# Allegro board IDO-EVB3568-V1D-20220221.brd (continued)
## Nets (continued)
S7TX_M1/RS485-B7: D87.1 D104.A(I/O2) F9.1 L44.2 R297.1
S7TX_M1_: F9.2 J36.2 TP11.1
SARADC_VIN0_KEY/RECOVERY: D33.1(I/O2) M5.15(SARADC_VIN0_KEY/RECOVERY) R62.1
SARADC_VIN2_HP_HOOK: C81.2 D35.1(I/O2) J13.3 M5.16(SARADC_VIN2_HP_HOOK) R70.2 R71.1
SARADC_VIN4: D36.1(I/O2) J13.4 M5.17(SARADC_VIN4) R60.2
SARADC_VIN5: D37.1(I/O2) J13.5 M5.18(SARADC_VIN5) R61.2
SATA1_RXN: C50.1 J6.5(RXN)
SATA1_RXP: C51.1 J6.6(RXP)
SATA1_TXN: C47.1 J6.3(TXN)
SATA1_TXP: C46.1 J6.2(TXP)
SCL_CAM: J28.7 R144.2
SD_CLK: C34.2 D9.1(I/O2) J3.5(CLK) R21.2
SD_CMD: D7.1(I/O2) J3.3(CMD) R20.2
SD_D0: D3.1(I/O2) J3.7(DATA0) R22.2
SD_D1: D4.1(I/O2) J3.8(DATA1) R23.2
SD_D2: D5.1(I/O2) J3.1(DATA2) R18.2
SD_D3: D6.1(I/O2) J3.2(CD/DATA3) R19.2
SDA_CAM: J28.8 R145.2
SDMMC0_CLK: M5.63(SDMMC0_CLK/TEST_CLKOUT/UART5_TX) R21.1
SDMMC0_CMD: M5.64(SDMMC0_CMD/PWM10_M1/UART5_RX_M0) R20.1
SDMMC0_D0: M5.68(SDMMC0_D0/UART2_TX_M1/UART6_TX_) R22.1
SDMMC0_D1: M5.67(SDMMC0_D1/UART2_RX_M1/UART6_RX_) R23.1
SDMMC0_D2: M5.66(SDMMC0_D2/ARMJTAG_TCK/UART5_CTS) R18.1
SDMMC0_D3: M5.65(SDMMC0_D3/ARMJTAG_TMS/UART5_RTS) R19.1
SDMMC0_DET_L: M5.62(SDMMC0_DET/SATA_CP_DET/PCIE30X1) R24.1
SDMMC2_CLK_M0: M5.92(CIF_D5/EBC_SDDO5/SDMMC2_CLK_M0/) R159.1
SDMMC2_CMD_M0: M5.93(CIF_D4/EBC_SDDO4/SDMMC2_CMD_M0/) R157.2 R158.1
SDMMC2_D0_M0: M5.97(CIF_D0/EBC_SDDO0/SDMMC2_D0_M0/I) R152.2 R153.1
SDMMC2_D1_M0: M5.96(CIF_D1/EBC_SDDO1/SDMMC2_D1_M0/I) R154.1
SDMMC2_D2_M0: M5.95(CIF_D2/EBC_SDDO2/SDMMC2_D2_M0/I) R155.1
SDMMC2_D3_M0: M5.94(CIF_D3/EBC_SDDO3/SDMMC2_D3_M0/I) R156.1
SIM_CLK: C271.2 D95.1(I/O2) R327.2 SIM1.C3(CLK) U36.32(UIM_CLK)
SIM_DATA: C262.2 D96.1(I/O2) R326.2 R339.1 SIM1.C7(DATA) U36.34(UIM_DATA)
SIM_DET: R325.1
SIM_RST: C272.2 D94.1(I/O2) R329.2 R330.1 SIM1.C2(RESET) U36.30(UIM_RESET)
SPI3_CLK_M1: D98.1(I/O2) J14.3 M5.27(PWM14_M1/SPI3_CLK_M1/CAN1_RX_M1)
SPI3_CS0_M1: D101.1(I/O2) J14.6 M5.31(PWM13_M1/SPI3_CS0_M1/SATA0_ACT_)
SPI3_MISO_M1: D100.1(I/O2) J14.5 M5.30(PWM12_M1/SPI3_MISO_M1/SATA1_ACT)
SPI3_MOSI_M1: D99.1(I/O2) J14.4 M5.28(PWM15_IR_M1/SPI3_MOSI_M1/CAN1_T)
SPK_5V: C92.2 C93.2 L21.2 U13.4(PVDD1) U13.13(PVDD2)
SPK_CTL_H_: Q1.3 U13.12(S\D\)
SPK_MUTE_H_: Q2.3 U13.5(M\U\T\E\)
SYS_LED_GPIO0_C7: M5.26(HDMITX_CEC_M1/PWM0_M1/UART0_CTS) R8.1
TP_INT: D64.1(I/O2) J24.4 R112.2
TP_INT_L_GPIO3_B4: M5.115(LCDC_D19/VOP_BT1120_D10/GMAC1_R) R112.1
TP_RST: D65.1(I/O2) J24.5 R111.2
TP_RST_L_GPIO3_B3: M5.116(LCDC_D18/VOP_BT1120_D9/GMAC1_RX) R111.1
TP_SCL: D63.1(I/O2) J24.3 R113.2
TP_SDA: D62.1(I/O2) J24.2 R114.2
UART0_RX: M5.19(PWM1_M0/GPUAVS/UART0_RX/GPIO0_C) R372.1 R383.1
UART0_RX_: R372.2 U27.9(R2OUT)
UART0_TX: M5.20(PWM2_M0/NPUAVS/UART0_TX/MCU_JTA) R278.1 U27.10(T2IN)
UART2_RX_M0: M5.60(UART2_RX_M0/GPIO0_D0_U) R26.1
UART2_TX_M0: M5.59(UART2_TX_M0/GPIO0_D1_U) R27.1
UART3_RX_M1: M5.111(LCDC_D23/PWM13_M0/GMAC1_MCLKINO) R370.1 R384.1
UART3_RX_M1_: R370.2 U26.12(R1OUT)
UART3_TX_M1: M5.112(LCDC_D22/PWM12_M0/GMAC1_TXEN_M0) R282.1 U26.11(T1IN)
UART4_RX_M1: M5.118(LCDC_D16/VOP_BT1120_D7/GMAC1_RX) R371.1 R385.1
UART4_RX_M1_: R371.2 U26.9(R2OUT)
UART4_TX_M1: M5.117(LCDC_D17/VOP_BT1120_D8/GMAC1_RX) R284.1 U26.10(T2IN)
UART5_RX_M1: D82.A M5.108(LCDC_DEN/VOP_BT1120_D15/SPI1_CL) R287.2 R373.1
UART5_RX_M1_: R373.2 U27.12(R1OUT)
UART5_TX_M1: D84.C M5.109(LCDC_VSYNC/VOP_BT1120_D14/SPI1_) R286.1 R288.1 U27.11(T1IN)
UART7_RX_M1: D86.A M5.106(PWM15_IR_M0/SPDIF_TX_M1/GMAC1_M) R294.2
UART7_TX_M1: D88.C M5.107(PWM14_M0/VOP_PWM_M1/GMAC1_MDC_M) R291.1 R295.1
UART8_CTSN_M0: M5.46(SDMMC1_DET/I2C4_SCL_M1/UART8_CT) R173.1 U23.41(UART_RTS_N)
UART8_RTSN_M0: M5.45(SDMMC1_PWREN/I2C4_SDA_M1/UART8_) U23.44(UART_CTS_N)
UART8_RX_M0: M5.58(CLK32K_OUT1/UART8_RX_M0/SPI1_CS) U23.42(UART_TXD)
UART8_TX_M0: M5.57(I2S2_SDI_M0/GMAC0_RXER/UART8_TX) U23.43(UART_RXD)
USB2_HOST2_DM: M5.99(USB2_HOST2_DM) R51.2
USB2_HOST2_DP: M5.100(USB2_HOST2_DP) R50.2
USB2_HOST3_DM: L7.2 M5.101(USB2_HOST3_DM)
USB2_HOST3_DM_: D18.2 D18.9 J8.2(1D-) L7.3
USB2_HOST3_DP: L7.1 M5.102(USB2_HOST3_DP)
USB2_HOST3_DP_: D18.1 D18.10 J8.3(1D+) L7.4
USB3_HOST1_DM: L6.1 M5.182(USB3_HOST1_DM)
USB3_HOST1_DM_: D15.5 D15.6 J5.11(2D-) L6.4
USB3_HOST1_DP: L6.2 M5.183(USB3_HOST1_DP)
USB3_HOST1_DP_: D15.4 D15.7 J5.12(2D+) L6.3
USB3_HOST1_SSRXN: C50.2 M5.185(USB3_HOST1_SSRXN/SATA1_RXN/QSGM) R32.1
USB3_HOST1_SSRXN_: D17.4 D17.7 J5.14(RX2-) R32.2
USB3_HOST1_SSRXP: C51.2 M5.184(USB3_HOST1_SSRXP/SATA1_RXP/QSGM) R33.1
USB3_HOST1_SSRXP_: D17.5 D17.6 J5.15(RX+) R33.2
USB3_HOST1_SSTXN: C40.1 C47.2 M5.181(USB3_HOST1_SSTXN/SATA1_TXN/QSGM)
USB3_HOST1_SSTXN_: C40.2 D16.4 D16.7 J5.17(TX2-)
USB3_HOST1_SSTXP: C42.1 C46.2 M5.180(USB3_HOST1_SSTXP/SATA1_TXP/QSGM)
USB3_HOST1_SSTXP_: C42.2 D16.5 D16.6 J5.18(TX2+)
USB3_OTG0_DM: L5.1 M5.188(USB3_OTG0_DM)
USB3_OTG0_DM_: D15.2 D15.9 J5.2(1D-) L5.4
USB3_OTG0_DP: L5.2 M5.189(USB3_OTG0_DP)
USB3_OTG0_DP_: D15.1 D15.10 J5.3(1D+) L5.3
USB3_OTG0_ID: M5.193(USB3_OTG0_ID)
USB3_OTG0_SSRXN: M5.191(USB3_OTG0_SSRXN/SATA0_RXN) R30.1
USB3_OTG0_SSRXN_: D17.1 D17.10 J5.5(RX1-) R30.2
USB3_OTG0_SSRXP: M5.190(USB3_OTG0_SSRXP/SATA0_RXP) R31.1
USB3_OTG0_SSRXP_: D17.2 D17.9 J5.6(RX1+) R31.2
USB3_OTG0_SSTXN: C36.1 M5.187(USB3_OTG0_SSTXN/SATA0_TXN)
USB3_OTG0_SSTXN_: C36.2 D16.1 D16.10 J5.8(TX1-)
USB3_OTG0_SSTXP: C37.1 M5.186(USB3_OTG0_SSTXP/SATA0_TXP)
USB3_OTG0_SSTXP_: C37.2 D16.2 D16.9 J5.9(TX1+)
USB3_OTG0_VBUSDET: M5.192(USB3_OTG0_VBUSDET) R28.1 R29.1
USB_OTG_PWREN_H: M5.61(SDMMC0_PWREN/SATA_MP_SWITCH/PCI) R34.1 U4.4(EN)
VOLN: C87.1 D46.1(I/O2) J17.4 L17.2 TP27.1
VOLP: C88.1 D45.1(I/O2) J17.3 L18.2 TP26.1
VORN: C90.1 D44.1(I/O2) J17.2 L19.2 TP25.1
VORP: C91.1 D43.1(I/O2) J17.1 L20.2 TP24.1
WIFI1T1R_CLK: C153.2 R159.2 U23.17(SDIO_DATA_CLK)
WIFI1T1R_CMD: R158.2 U23.16(SDIO_DATA_CMD)
WIFI1T1R_D0: R153.2 U23.18(SDIO_DATA_0)
WIFI1T1R_D1: R154.2 U23.19(SDIO_DATA_1)
WIFI1T1R_D2: R155.2 U23.14(SDIO_DATA_2)
WIFI1T1R_D3: R156.2 U23.15(SDIO_DATA_3)
WIFI1T1R_XTAL_IN: C155.1 U23.10(XTAL_IN) XT3.3
WIFI1T1R_XTAL_OUT: R163.2 U23.11(XTAL_OUT)
WIFI_REG_ON_H_GPIO3_D4: M5.91(CIF_D6/EBC_SDDO6/SDMMC2_DET_M0/) R168.1 R182.1
WIFI_WAKE_HOST_H_GPIO3_D5: M5.90(CIF_D7/EBC_SDDO7/SDMMC2_PWREN_M) U23.13(WL_HOST_WAKE)
WIFIBT_32KIN_1T1R: C168.2 R176.2 R177.2 U23.24(LPO)
N17052705: R179.1 U23.29(VDD_TCXO)
N17052995: R181.2 R182.2 U23.34(BT_RST_N)
N17053074: C154.2 C156.2 U23.2(WL_BT_ANT)
N17053234: C154.1 C157.2 J29.2(SIG)
N17053342: C167.2 C491.2 L31.2 U23.23(VIN_LDO)
N17053374: C158.2 R163.1 XT3.1
N17053434: L31.1 U23.21(VIN_LDO_OUT)
N17846666: R215.1 U24.31(INTB/PMEB)
N67123537: R35.1 U4.3(OCB)
N67146313: R46.1 U8.43(OVCJ5) U8.45(OVCJ1)
N67159131: R41.1 U6.3(OCB)
N67228394: C2.1 L1.1 U1.2(LX)
N67228398: C2.2 U1.4(BS)
N67228404: C8.1 R4.2 R6.1 U1.6(FB)
N67269040: D60.A L28.2 U16.1(LX)
N67928236: C218.2 U26.1(C1+)
N67928238: C218.1 U26.3(C1-)
N67928242: C219.2 U26.4(C2+)
N67928244: C219.1 U26.5(C2-)
N67928270: C220.2 U26.2(V+)
N67928274: C221.2 U26.6(V-)
N68112138: R37.1 U5.3(OCB)
N68117516: D12.1(I/O2) J4.2 R27.2
N68117520: D10.C D11.1(I/O2) J4.1
N68117689: D10.A R25.2 R26.2
N68120764: D49.C R82.1 R84.1
N68141872: R115.1 U16.3(FB)
N68149060: R62.2 SW1.1
N68226715: L34.1 U26.14(T1OUT)
N68226717: L35.1 U26.13(R1IN)
N68226719: L36.1 U26.7(T2OUT)
N68226721: L37.1 U26.8(R2IN)
N68234263: D38.1(I/O2) J15.3(R) R76.2
N68234265: D40.1(I/O2) J15.2(L) R73.2
N68234885: C80.2 R68.2 R69.1
N68235937: D39.1(I/O2) J15.5(L-COM) R74.2
N68290667: L18.1 U13.1(VOLP)
N68290669: L17.1 U13.3(VOLN)
N68290717: L19.1 U13.14(VORN)
N68290719: L20.1 U13.16(VORP)
N68290721: C86.1 R79.1
N68290723: R79.2 U13.7(INL)
N68290736: C89.1 R80.1
N68290738: R80.2 U13.10(INR)
N68290823: C85.2 U13.8(BYPASS)
N68391184: R14.2 U2.1(EN)
N68391237: L2.1 U2.3(SW)
N68391239: C19.1 R12.2 R15.1 U2.5(FB)
N68444772: C488.2 D1.C F1.2 L50.2 R368.1
N68540703: R262.1 U25.31(INTB/PMEB)
N68550545: C126.2 C129.2 U17.11(VCORE)
N68551303: R121.2 U17.8(I2C_TYPE)
N68551306: R122.2 U17.12(EN)
N68551396: R120.2 U17.7(I2C_ADDR)
N68552374: C141.1 Q9.1(GATE) R129.2 R131.2
N68552446: Q10.3 R131.1
N68558276: R104.1 U15.3(FB)
N68558638: D56.A L27.2 U15.1(LX)
N68563618: C239.1 U34.1(OSCI) XT6.1
N68563661: C240.1 U34.2(OSCO) XT6.2
N68582360: C111.1 Q6.1(GATE) R90.2 R91.2
N68582430: Q7.3 R91.1
N68600227: J41.10(USIM_IO) R326.1
N68600229: J41.12(USIM_CLK) R327.1
N68600231: J41.14(USIM_RESET) R329.1
N68600309: J41.8(VREG_USIM) L48.1
N68610828: C165.1 Q12.1(GATE) R175.2 R178.2
N68611164: Q13.3 R178.1
N68644173: R168.2 U23.12(WL_REG_ON)
N68693421: R43.1 U7.3(OCB)
N68696061: R49.1 U9.3(OCB)
N68696295: R53.1 U10.3(OCB)
N68706836: R57.1 U11.3(OCB)
N68707388: R59.1 U12.3(OCB)
N68721096: R325.2 U36.66(SIM1_DETECT_(1V8))
N68721887: R342.2 U37.1(EN)
N68721931: L49.1 U37.3(SW)
N68721933: C265.1 R340.2 R341.1 U37.5(FB)
N68723170: C252.2 R337.2 R338.1 U36.6(FUL_CARD_P/OWER_OFF#_(3V3/1V8))
N68753609: R321.2 U35.24(SDA/SDI)
N68753612: R322.1 U35.22(NCS)
N68753720: R320.2 U35.23(SCL/SCLK)
N68753740: TP1.1 U35.12(INT)
N68754791: C245.2 U35.10(REGOUT)
N68764417: C16.1 L3.1 U39.2(LX)
N68764421: C16.2 U39.4(BS)
N68764430: C24.1 R13.2 R17.1 U39.6(FB)
N68782340: R149.2 U19.3(EN)
N68782427: R150.2 U20.3(EN)
N68782451: R151.2 U21.3(EN)
N68784083: C83.2 R75.2 R78.1
N68821934: LED1.1 R8.2
N68821936: LED1.3 R9.2
N68825811: LED2.A(ANODE) R334.2
N68865571: C227.2 D84.A R288.2 U28.2
N68866830: C230.2 D88.A R295.2 U30.2
N68869057: C223.2 U27.1(C1+)
N68869059: C223.1 U27.3(C1-)
N68869063: C224.2 U27.4(C2+)
N68869065: C224.1 U27.5(C2-)
N68869069: C225.2 U27.2(V+)
N68869073: C226.2 U27.6(V-)
N68869089: L38.1 U27.14(T1OUT)
N68869091: L39.1 U27.13(R1IN)
N68869093: L40.1 U27.7(T2OUT)
N68869095: L41.1 U27.8(R2IN)
N68871128: C235.2 R303.2 R304.2
N68871171: C234.2 R300.2 U32.5(VIO/NC)
N68877118: C238.2 R310.2 R311.2
N68877190: C237.2 R367.2 U33.5(VIO/NC)
N68886075: C202.2 J31.1(CT1/2/3/4)
N68888039: C179.2 J30.1(CT1/2/3/4)
N69126369: J41.22(PERST_N) R376.1
N69153757: C12.2 R3.2 R5.1 U39.5(EN)
N69164567: R16.2 U1.5(EN)
N69167857: R381.1 U40.3(OCB)
N69206132: R386.1 R389.2 U19.4(NC)
N69206262: C492.2 R387.2 R388.1 U20.4(NC)
N69206971: R390.1 R391.2 U21.4(NC)

Pads without a net: D71 5; D72 5; D73 5; D74 5; J2 5 6; J15 6; J18 14; J19 3 5 6; J22 3 4 5 6 7 8 12 13 14 15 17 18 35 40; J23 3 4 5 6 7 8 12 13 14 15 17 18 35 40; J26 4; J41 1 3 5 6 7 11 13 16 17 19 20 23 25 28 30 31 32 33 44 45 46 47 48 49 51; M1 1; M2 1; M3 1; M4 1; M5 205 206 207; SIM1 C6 CD1 CD2; U8 1 2 3 4 5 7 44 46 47 48; U17 1 2 3 4 6; U23 4 5 8 25 26 27 28 30 32 35 37 38 39 40 45 46 47; U28 1; U30 1; U34 3; U35 1 2 3 4 5 6 7 14 15 16 17 19 21; U36 1 7 8 9 10 20 21 22 23 24 25 26 28 29 31 35 37 38 40 42 44 46 48 50 52 54 56 58 59 60 61 62 63 64 65 68 69 75

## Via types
v1: diameter 0.55, hole 0.3, TOP to BOTTOM, 807 vias
v2: diameter 0.406, hole 0.203, TOP to BOTTOM, 1303 vias

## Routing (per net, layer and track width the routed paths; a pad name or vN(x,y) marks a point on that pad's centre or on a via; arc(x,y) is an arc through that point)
GND: length 3029.4
  TOP w0.127: v2(91.08,25.53) 91.44,25.88 91.44,27.94 92.46,28.96 92.46,37.59 92.96,38.1 92.96,41.02 92.46,41.53 92.46,50.52 93.09,51.16 93.09,51.61 93.91,52.43 v2(94.59,52.43) ; v2(76.83,24.49) v2(76.83,25.65) 76.83,26.16 77.22,26.54 80.01,26.54 87.88,34.42 87.88,53.19 v2(88.04,53.34) 88.04,54 88.27,54.23 88.77,54.23 88.9,54.1 88.9,53.37 v2(88.87,53.34) 88.87,53.19 88.39,52.7 88.39,34.16 80.26,26.04 79.01,26.04 v2(78.87,25.9) 78.49,25.51 78.49,25.15 78.87,24.77 80.14,24.77 81.41,26.04 ; M5.98 96.8,64.24 99.59,61.44 v2(99.59,59.44) ; v2(89.66,26.04) 89.66,27.69 91.44,29.46 91.44,38.23 91.69,38.48 v1(91.69,38.95) ; v2(90.73,24.54) 90.73,24.84 90.42,25.15 90.42,27.69 91.95,29.21 91.95,37.85 92.46,38.35 92.46,40.77 91.95,41.27 91.95,50.73 92.58,51.37 92.58,51.82 94.16,53.39 v2(94.34,53.39) ; v2(92.96,62.99) 94.36,61.59 94.36,53.42 v2(94.34,53.39) ; v2(95.76,22.05) 95.76,22.99 96.52,23.75 97.54,23.75 98.3,24.51 98.3,31.37 99.19,32.26 99.19,43.43 102.49,46.74 115.21,46.74 116.61,48.13 126.75,48.13 126.98,48.36 127,48.36 127.77,49.14 127.77,49.16 ; v2(94.34,53.39) 94.74,52.98 94.74,52.58 v2(94.59,52.43) ; 81.41,26.04 89.15,33.78 89.15,52.2 89.79,52.83 89.79,53.21 91.44,54.86 91.44,55.88 91.19,56.13 91.19,58.17 91.72,58.7 v2(91.92,58.7) 92.29,58.33 92.29,57.87 91.97,57.55 v2(91.89,57.55) 91.69,57.35 91.69,56.52 92.08,56.13 92.08,54.74 90.3,52.96 90.3,52.58 89.66,51.94 89.66,33.53 88.77,32.64 88.77,32.13 v2(83.82,27.18) 82.55,25.91 v2(81.92,25.91) 81.53,25.91 81.41,26.04 ; v2(91.97,17.53) 91.99,17.51 92.72,17.51 v2(92.99,17.78) ; v2(73.03,32.51) 73.53,32.51 73.83,32.22 73.83,31.87 72.57,30.61 59.44,30.61 55.02,26.19 v2(55.02,25.91) ; v2(92.77,61.81) 93.85,60.72 93.85,53.85 92.08,52.07 92.08,51.69 91.44,51.05 91.44,40.34 91.69,40.09 v1(91.69,39.62) ; v2(101.5,52.4) 100.97,51.87 100.97,50.6 100.18,49.81 v2(100.18,49.55) ; v2(94.59,52.43) 94.74,52.27 94.74,51.82 94.41,51.49 94.36,51.49 ; 94.36,51.49 94.6,51.24 v2(94.6,50.5) 93.73,49.62 v2(93.73,48.13) v2(93.73,47.12) 93.73,46.72 93.47,46.47 93.47,42.04 94.11,41.4 94.11,38.69 v2(94.27,38.52) ; 94.36,51.49 v2(93.95,51.49) 93.6,51.13 93.6,50.93 92.96,50.29 92.96,41.78 93.47,41.27 93.47,38.18 v2(93.96,37.69) ; v2(97.71,21.69) 97.89,21.69 99.82,23.62 99.82,30.61 100.71,31.5 100.71,42.67 103.25,45.21 115.95,45.21 117.35,46.61 128.42,46.61 129.54,45.49 129.54,41.02 131.32,39.24 ; v1(108.33,58.93) 108.7,59.3 U23.20 108.7,60.97 108.43,61.24 108.43,64.74 108.2,64.97 103.2,64.97 103,64.77 103,60.96 103.53,60.43 103.53,60.15
  TOP w0.152: 14.38,21.86 17.4,24.88 C113.1
  TOP w0.203: v2(122.17,60.17) 122.17,59.62 122.15,59.59 122.15,59.43 122.12,59.41 122.12,59.03 121.21,58.12 118.64,58.12 v2(118.29,57.76) ; 123.75,44.02 124.03,43.74 126.72,43.74 126.95,43.5 126.95,39.7 126.75,39.5 124.61,39.5 v2(124.19,39.92) C239.2 123.22,40.89 120.65,40.89 120.51,41.04 120.51,43.16 120.65,43.31 121.74,43.31 U34.4 ; XT3.2 122.43,61.47 v2(122.68,61.72) 122.68,63.88 122.45,64.11 121.01,64.11 v2(120.65,63.75) 120.06,63.17 XT3.4 118.85,62.99 118.57,62.99 118.26,62.69 118.26,62.65 v2(118.11,62.65) 118.16,62.6 118.24,62.6 118.26,62.58 118.26,59.36 v2(118.32,59.31) ; v2(12.17,27.1) 12.17,31.57 v2(12.34,31.75) ; v1(27.41,49.4) 26.81,49.4 U39.3
  TOP w0.254: 47.88,20.07 49.53,20.07 v2(52.07,20.07) v2(56.52,20.07) 59.18,20.07 59.94,19.3 v2(60.2,19.3) v2(61.72,19.3) 63.75,19.3 v2(64.52,18.54) 65.58,17.48 71.25,17.48 v2(71.73,16.99) ; Q7.2 89.41,13.71 89.66,13.96 ; v2(12.34,31.75) 15.82,31.75 18.11,34.04 18.11,35.61 18.44,35.94 U33.2 ; v2(51.94,22.5) v2(53.34,22.5) 53.37,22.5 v2(54.99,22.5) v2(56.64,22.5) v2(57.91,22.5) v2(59.56,22.5) 60.05,22.5 60.83,21.72 65.91,21.72 67.64,19.99 v2(75.69,19.99) v2(87.88,19.99) v2(88.52,19.99) 88.7,19.99 89.08,19.61 91.39,19.61 91.74,19.25 97.59,19.25 v2(98.3,18.54) 101.73,15.11 103.38,15.11 103.91,14.58 D38.2 ; C131.1 29.66,22.28 v2(29.79,22.4) ; 95.58,3.78 95.53,3.78 94.49,4.83 94.49,5.71 92.58,7.62 92.58,12.19 91.34,13.44 D41.2 ; 95.58,3.78 99.77,3.78 ; 95.58,3.78 95.58,1.98 95.12,1.52 92.71,1.52 92.46,1.78 92.46,3.68 93.6,4.83 93.6,5.33 91.82,7.11 91.82,11.81 90.37,13.26 90.26,13.26 90.24,13.28 89.99,13.28 89.98,13.28 89.97,13.28 89.66,13.59 89.66,13.96 ; 89.66,13.96 v2(89.66,14.22) ; U17.37 19.81,19.68 ; v2(92.99,17.78) 93.24,18.03 95.89,18.03 97.03,16.89 v2(97.03,16.74) 97.18,16.74 98.55,15.37 98.55,14.43 R77.2 ; v2(91.97,17.53) 91.92,17.48 87.35,17.48 v2(86.97,17.09) 86.64,16.76 83.19,16.76 82.47,17.48 76.02,17.48 v2(75.82,17.27) 75.62,17.48 72.72,17.48 v2(72.26,17.02) ; U39.3 26.79,49.9 27.05,50.16 ; M5.14 50.39,23.85 58.8,32.26 v2(67.18,32.26) 67.31,32.38 71.5,32.38 71.63,32.51 v2(73.03,32.51)
  TOP w0.305: v2(112.65,24) 112.69,23.96 U36.57 ; J18.8 v1(28.65,94.49) ; U36.5 v2(125.69,23.88) ; U36.11 v2(124.19,23.86) ; J18.11 v1(30.15,94.49) ; v1(33.15,94.49) J18.17 33.15,91.06 v1(33.4,90.81) ; v1(60.66,84.79) 60.16,85.28 C6.1 ; v1(54.83,85.18) C10.1 v1(54.83,83.25) C11.1 54.83,81.95 v1(55.37,81.41) ; J18.2 v1(25.65,94.49) ; v2(126.19,23.88) U36.3 ; U18.3 29.46,12.25 29.21,12.5 ; U36.73 v2(108.69,23.9) ; U36.71 v2(109.19,23.9) ; U36.45 v2(115.69,23.87) ; U17.9 23.81,23.81 U17.49 23.31,21.81 U17.5 ; U36.51 v2(114.19,21.61) ; J18.5 v1(27.15,94.49)
  TOP w0.381: v2(121.79,17.27) 122.2,17.27 D9.2 ; v2(11.99,52.86) 11.91,52.86 11.46,52.4 C228.1 ; v2(91.62,80.31) U10.2 v2(93.4,80.31) ; 101.9,4.11 J15.1 100.81,2.75 99.77,3.78 ; D43.2 v2(114.17,11.94) ; D14.2 52.88,84.62 v2(52.81,84.69) ; v2(104.44,68.05) 104.17,68.05 R195.1 104.14,68 103.41,67.26 C190.1 ; v2(122.17,60.17) C155.2 121.46,60.66 121.82,61.02 XT3.2 ; v2(118.49,27.69) 119.18,27.69 119.45,27.41 J41.27 ; v2(108.03,23.89) 107.99,23.89 107.99,23.89 107.45,23.89 U36.MTG77 v2(107.1,21.88) ; v2(114.83,68.2) 115.21,68.58 C196.1 ; v2(123.88,18.85) 124.32,18.85 124.52,18.64 C35.1 124.4,18.41 124.24,18.26 v2(123.88,18.26) ; v2(112.62,71.93) 112.62,71.88 112.37,71.63 111.63,71.63 v2(111.46,71.45) ; C222.1 21.77,64.09 v2(21.94,64.26) ; U36.39 117.19,21.87 v2(117.6,21.46) ; J41.15 111.76,26.08 112.14,26.46 v2(112.14,26.8) ; D69.3 21.64,13.74 v2(21.49,13.89) ; v2(130.68,25.65) 131.95,25.65 132.3,26 J41.55 ; J17.5 v2(115.99,4.19) ; J17.5 117.34,2.02 ; J17.5 114.82,2.02 ; J34.1 7.52,54 v2(8.33,53.19) ; D70.3 v2(15.54,13.92) ; J41.50 v2(128.65,35.62) 128.59,35.69 v2(128.14,35.69) v2(127.51,35.69) 127.25,35.69 ; 13.13,24.89 13.26,24.89 v1(13.56,25.2) ; 13.13,24.89 v1(13.56,24.46) ; 13.13,24.89 U15.2 ; R301.1 11.58,43.35 v1(11.58,43.35) 11.58,44.02 C234.1 ; v2(7.37,17.99) 6.31,17.99 5.92,17.61 J39.3 ; v2(118.93,14.93) J3.10 v2(118,13.83) ; D48.3 D48.8 v1(29.46,90.58) ; U23.31 v2(104.65,51.55) 104.58,51.55 R161.2 ; C82.1 v2(97.03,16.74) ; v2(116.43,73.3) 117.2,72.54 R259.1 ; R307.1 11.3,35.05 11.69,35.43 v2(12.29,35.43) ; J41.26 v2(119.05,35.53) ; U33.2 20.39,35.94 20.45,35.99 C236.1 v2(21.03,35.08) ; J33.6 v2(2.17,74.17) ; v2(128.78,24.7) 128.21,24.7 127.8,24.3 U36.MTG76 ; J41.37 v2(123.45,24.77) ; v1(73.66,82.25) 73.46,82.45 D18.3 D18.8 ; U36.MTG76 127.8,22.95 128.14,22.61 v2(128.78,22.61) ; U36.MTG76 v2(128.78,23.55) ; v2(92.43,76.61) 92.43,77.07 R53.2 ; v2(109.35,73.91) 108.99,73.56 C189.1 ; v2(133.53,12.7) J3.11 v2(134.73,13.83) ; v2(114.05,39.75) C263.1 ; J41.34 122.25,35.46 v2(122.05,35.66) ; v2(1.52,78.65) 1.52,78.61 2.17,77.96 J32.5 ; v2(104.8,49.75) U23.33 ; v2(95.19,82.3) C61.1 v2(95.81,83.06) ; v2(13.03,55.55) U29.5 v2(15.06,55.55) ; J39.6 v2(4.31,10.8) ; C226.1 v2(11.43,58.29) ; v2(104.54,25.54) 104.4,25.54 103.26,26.68 J41.56 102.23,25.91 v2(101.49,25.91) ; D8.2 v2(118.11,18.67) ; J3.13 v2(135.51,4.13) ; J3.13 v2(134.43,5.65) ; J3.13 v2(133.42,4.13) ; v2(117.59,27.69) 117.05,27.15 J41.21 ; 103.53,59.76 103.33,59.56 C491.1 ; J34.6 v2(4.21,62.35) ; M5.38 74.39,25.2 v2(74.19,25.4) ; R242.1 116.16,67.52 v2(115.54,66.9) ; v2(100.08,85.34) v2(100.08,84.2) C173.1 ; v2(97.92,78.87) 97.17,79.61 C62.1 96.79,79.61 96.76,79.64 96.51,79.64 v2(96.14,80.01) ; v2(103.5,73.53) 103.17,73.2 C172.1 ; C131.1 R121.1 29,21.31 v2(29.79,20.52) ; v1(31.11,89.41) 30.99,89.53 v1(30.99,90.55) ; v2(18.34,41.73) 18.49,41.58 U32.2 ; J4.3 v2(113.26,16.49) ; v2(102.36,55.63) 102.62,55.88 C168.1 ; J35.6 v2(4.31,49.39) ; D66.3 v2(27.74,13.87) ; v2(102.49,53.42) 102.54,53.42 102.62,53.34 R179.2 ; D41.2 91.46,13.97 v2(92.84,13.97) ; D46.2 v2(107.09,11.97) ; R246.1 v2(115.22,70.97) ; M5.127 70.39,69.57 71.45,68.5 v2(71.75,68.5) ; v2(100.08,75.69) R203.1 ; C166.1 124.27,57.4 123.89,57.02 v2(123.62,57.02) ; D33.2 v2(142.88,95.25) ; D6.2 v2(128.63,18.82) ; C85.1 v2(94.11,15.24) ; J41.4 107.05,35.68 v2(107.82,36.45) ; D17.3 D17.8 ; J36.5 v2(4.32,25.74) ; v2(139.42,95.98) R239.2 v2(139.42,94.64) ; J41.43 v2(125.85,24.77) ; J41.29 v2(120.25,24.65) 120.25,24 120.19,23.94 U36.27 ; v2(123.83,19.84) 124.24,19.84 124.52,20.12 C266.1 124.46,20.19 v2(123.7,20.95) ; D44.2 v2(111.23,11.92) ; M5.105 v1(92.39,71.08) ; J33.5 v2(2.17,63.5) ; v2(124.99,70.79) 125.04,70.84 125.58,70.84 C213.1 ; 103.53,59.77 v2(103.53,59.79) 103.5,59.79 ; 104.02,2.02 J17.6 104.39,2.92 v2(104.2,2.92) ; U34.4 123.08,43.29 123.17,43.2 C240.2 v2(123.75,44.32) ; U26.15 17.93,69.6 ; v2(11.46,46.79) 11.46,46.31 C232.1 ; D3.2 v2(120.85,18.72) ; D47.3 D47.8 v1(25.91,90.55) ; J3.6 v2(123.43,16.12) ; v2(88.7,85.38) D21.8 D21.3 ; v2(15.32,11.66) 15.54,11.89 D70.8 ; J41.18 v2(115.85,35.66) ; U27.15 v2(20.17,62.89) ; C94.1 v2(97.54,12.32) ; C126.1 C129.1 28.93,24.74 v2(29.34,25.15) ; v2(118.36,21.34) 118.69,21.66 U36.33 ; v2(129.67,18.8) 129.79,18.67 D5.2 ; C175.1 110.46,68.35 110.17,68.05 109.98,67.87 109.98,67.87 v2(109.75,67.64) 109.73,67.64 109.6,67.77 v2(108.94,67.77) ; v1(105.79,38.68) 105.41,38.3 C246.1 ; 119.18,59.31 v2(118.32,59.31) ; C80.1 v2(90.38,16.72) ; v2(98.93,75.69) R192.2 ; D4.2 v2(119.48,18.77) ; v2(69.72,14.22) 70.5,14.22 70.88,14.61 U14.3 ; J41.55 132.3,27.46 131.95,27.81 v2(130.68,27.81) ; J41.55 v2(130.69,26.68) ; J4.4 v2(114.3,14.78) ; J4.4 v2(117.3,14.78) ; J4.4 v2(115.81,12.84) ; D69.8 v2(21.64,11.66) ; D67.3 v2(18.59,13.92) ; R299.2 v2(21.41,51.48) ; J41.35 v2(122.65,24.77) ; J41.40 124.65,35.23 v2(124.28,35.6) ; U31.5 v2(15.37,49.91) ; v2(108.84,16.64) 108.84,16 108.21,15.38 J4.5 108.84,14.16 v2(108.84,12.95) ; v2(94.74,15.31) D39.2 ; J36.1 v2(1.8,28.09) ; v2(124.26,17.22) 124.67,17.22 D2.2 ; J34.5 v2(4.28,51.65) ; R173.2 v2(102.13,48.26) ; v2(126.3,37.91) 126.3,38.61 126.26,38.65 v2(125.56,38.65) C253.1 124.19,38.65 v2(123.95,38.4) ; J32.6 3.78,88.26 v2(4.32,88.8) ; C221.1 v2(11.43,65.05) ; D68.3 v2(24.69,13.82) ; D67.8 v2(18.59,11.68) ; J41.9 v2(109.05,27.43) ; D68.8 v2(24.69,11.66) ; D45.2 v2(110.13,10.44) ; C259.1 127.41,19.48 v2(127.41,18.77) D7.2 ; R71.2 v2(89.76,16) ; D66.8 v2(27.74,11.66) ; C486.1 v1(22.57,42.43) ; J3.12 118.93,2.61 ; R293.2 v2(20.24,52.66) ; v2(89.74,16.94) C81.1 ; R52.2 v2(93.47,77.14) ; D23.2 v2(95.63,84.58)
  TOP w0.508: J5.13 47.9,89.31 48.26,89.66 ; v1(27.69,84.84) v1(27.69,84.07) v1(27.69,83.31) 27.69,83.05 ; v1(33.15,94.49) v1(32.51,94.49) v1(31.75,94.49) v1(30.86,94.49) v1(30.15,94.49) v1(29.46,94.49) v1(28.65,94.49) v1(27.94,94.49) v1(27.15,94.49) v1(26.42,94.49) v1(25.65,94.49) v1(24.89,94.49) 24.51,94.49 v1(24.26,94.23) v1(24.26,93.47) v1(24.26,92.58) v1(24.26,91.69) v1(24.26,90.93) v1(24.26,90.17) v1(24.26,89.41) 23.88,89.03 v1(23.88,88.65) v1(23.88,87.88) v1(23.88,87.12) v1(23.88,86.36) v1(23.88,85.6) ; v1(24.38,84.84) v1(24.38,84.07) v1(24.38,83.31) 24.38,83.05 ; v1(29.46,84.84) v1(29.46,84.07) v1(29.46,83.31) 29.46,82.93 ; v1(27.69,88.9) v1(27.69,89.66) v1(27.69,90.55) ; v1(31.11,83.31) v1(31.11,84.07) v1(31.11,84.84) 31.5,85.22 v1(31.5,85.6) v1(31.5,86.36) v1(31.5,87.12) v1(31.5,87.88) v1(31.5,88.65) 31.5,89.03 v1(31.11,89.41) ; v1(25.91,84.84) v1(25.91,84.07) v1(25.91,83.31) 25.91,83.18 ; C167.1 103.53,60.15 v2(103.53,59.79) ; J32.1 v1(1.52,79.91)
  TOP w0.686: 27.99,9.14 J26.13 27.17,8.32 ; J14.2 142.01,14.81 ; J14.2 142.01,13.18 ; J14.2 141.2,14 ; J14.2 142.82,14 ; 44.27,6.25 J27.2 ; J27.2 45.21,5.31 ; J27.2 45.21,7.19 ; 57.17,87.25 J5.19 ; J5.19 58.74,88.83 ; J5.19 57.17,90.4 ; J5.19 55.59,88.83 ; J18.20 36.9,95.3 ; J18.20 37.82,93.37 ; J18.20 35.97,93.37 ; J18.20 36.9,91.44 ; J8.S4 65.31,94.02 ; J8.S4 63.69,95.65 ; J8.S4 63.69,92.39 ; J8.S4 62.06,94.02 ; J6.1 64.24,75.92 ; J6.1 63.6,75.11 ; J6.1 62.96,75.92 ; J6.1 63.6,76.73 ; 80.35,88.34 J9.S2 ; J9.S2 81.97,89.97 ; J9.S2 83.6,88.34 ; J9.S2 81.97,86.72 ; J26.26 15.17,7.97 ; J26.26 15.99,7.14 ; J26.26 15.17,6.32 ; J26.26 14.34,7.14 ; 142.06,40.21 J13.6 ; J13.6 142.06,41.83 ; J13.6 141.25,41.02 ; J13.6 142.88,41.02 ; J6.9 54.66,76.42 ; J6.9 51.96,76.42 ; J6.9 53.31,75.07 ; J6.9 53.31,77.77 ; J27.1 43.18,7.19 ; J27.1 43.18,5.31 ; J27.1 44.12,6.25 ; J27.1 42.24,6.25 ; J8.S3 78.46,94.02 ; J8.S3 76.83,95.65 ; J8.S3 75.2,94.02 ; J8.S3 76.83,92.39 ; 129.69,75 H5.1 ; H5.1 132.87,78.18 ; H5.1 126.51,78.18 ; H5.1 129.69,81.36 ; 75.2,88.34 J8.S1 ; J8.S1 78.46,88.34 ; J8.S1 76.83,89.97 ; J8.S1 76.83,86.72 ; 93.49,88.34 J9.S1 ; J9.S1 96.74,88.34 ; J9.S1 95.12,86.72 ; J9.S1 95.12,89.97 ; 35.99,9.14 J26.5 35.17,9.97 ; 35.17,6.32 J26.6 ; J26.6 34.34,7.14 ; J26.6 35.99,7.14 ; 36.9,97.9 J18.23 ; J18.23 37.82,99.33 ; J18.23 35.97,99.33 ; J18.23 36.9,100.76 ; J5.22 58.74,94.51 ; J5.22 57.17,96.08 ; J5.22 57.17,92.93 ; J5.22 55.59,94.51 ; 123.39,87.32 J31.10 122.45,86.38 ; J12.4 141.96,73.69 ; J12.4 141.96,72.06 ; J12.4 142.77,72.87 ; J12.4 141.15,72.87 ; J11.4 141.99,63.14 ; J11.4 141.17,62.33 ; J11.4 141.99,61.52 ; J11.4 142.8,62.33 ; J10.4 142.9,51.69 ; J10.4 141.27,51.69 ; J10.4 142.09,52.5 ; J10.4 142.09,50.88 ; 66.08,91.34 J8.4 ; J8.4 66.76,90.66 ; J8.4 67.43,91.34 ; J8.4 66.76,92.02 ; 142.06,30.05 J13.1 ; J13.1 142.06,31.67 ; J13.1 142.88,30.86 ; J13.1 141.25,30.86 ; J5.7 51.33,91.01 ; J5.7 50.6,91.74 ; J5.7 50.6,90.27 ; J5.7 49.86,91.01 ; J8.S2 65.31,88.34 ; J8.S2 63.69,86.72 ; J8.S2 63.69,89.97 ; 15.99,9.14 J26.25 15.17,8.32 ; J6.7 55.98,76.73 ; J6.7 55.98,75.11 ; J6.7 55.34,75.92 ; J6.7 56.62,75.92 ; 142.01,25.37 J14.8 ; J14.8 142.82,26.19 ; J14.8 141.2,26.19 ; J14.8 142.01,27 ; 93.49,94.02 J9.S3 ; J9.S3 95.12,92.39 ; J9.S3 95.12,95.65 ; J9.S3 96.74,94.02 ; 72.46,7.14 J19.4 ; J19.4 73.29,7.97 ; J19.4 74.11,7.14 ; 14.45,94.44 LED1.4 ; LED1.4 16.23,94.44 ; LED1.4 15.34,95.33 ; LED1.4 15.34,93.55 ; 15.34,96.09 LED1.2 ; LED1.2 15.34,97.87 ; LED1.2 14.45,96.98 ; LED1.2 16.23,96.98 ; J18.21 22.4,95.3 ; J18.21 23.32,93.37 ; J18.21 21.47,93.37 ; J18.21 22.4,91.44 ; 80.39,6.25 J21.2 81.33,5.31 ; 139.81,101.16 SW1.3 ; SW1.3 141.47,101.16 ; SW1.3 140.64,100.33 ; J5.21 45.6,94.51 ; J5.21 44.03,92.93 ; J5.21 44.03,96.08 ; J5.21 42.45,94.51 ; 46.36,92.51 J5.4 ; J5.4 47.83,92.51 ; J5.4 47.1,93.24 ; 21.47,99.33 J18.22 ; J18.22 23.32,99.33 ; J18.22 22.4,97.9 ; J18.22 22.4,100.76 ; U36.MH1 117.44,80.91 ; U36.MH1 120.61,77.73 ; U36.MH1 117.44,74.55 ; 85.04,90.66 J9.4 ; J9.4 85.72,91.34 ; J9.4 85.04,92.02 ; J9.4 84.37,91.34 ; 78.36,6.25 J21.1 ; J21.1 79.3,5.31 ; J21.1 80.24,6.25 ; J19.13 63.29,9.97 ; J19.13 64.11,9.14 ; J19.13 63.29,8.32 ; 66.08,88.7 J8.13 ; J8.13 66.76,89.38 ; J8.13 66.76,88.02 ; J8.13 67.43,88.7 ; 80.35,94.02 J9.S4 ; J9.S4 83.6,94.02 ; J9.S4 81.97,95.65 ; J9.S4 81.97,92.39 ; 84.37,88.7 J9.13 ; J9.13 85.04,88.02 ; J9.13 85.04,89.38 ; J9.13 85.72,88.7 ; 62.46,7.14 J19.14 ; J19.14 64.11,7.14 ; J19.14 63.29,7.97 ; J7.2 74.52,77.55 ; J7.2 73.58,76.61 ; J7.2 75.46,76.61 ; J7.2 74.52,75.67 ; 66.27,77.77 J6.8 64.92,76.42 ; 59.79,75.11 J6.4 ; J6.4 59.15,75.92 ; J6.4 59.79,76.73 ; J6.4 60.43,75.92 ; J30.10 102.49,88.26 ; J30.10 102.49,86.38 ; J30.10 101.55,87.32 ; J30.10 103.43,87.32 ; 50.6,87.07 J5.16 ; J5.16 49.86,87.81 ; J5.16 50.6,88.54 ; 45.6,88.83 J5.20 44.03,87.25 ; 27.17,6.32 J26.14 ; J26.14 27.17,7.97 ; J26.14 26.34,7.14 ; J26.14 27.99,7.14 ; 135.97,11.94 J16.1 ; J16.1 137.85,11.94 ; J16.1 136.91,11 ; 139.09,98.38 SW1.2 ; SW1.2 139.92,99.21 ; SW1.2 139.09,100.04 ; SW1.2 138.26,99.21
  TOP w1.016: J26.6 J26.5
  VCC w0.686: J26.25 15.84,9.14 ; J26.25 15.17,9.82 ; J26.25 15.17,8.47 ; J26.25 14.49,9.14 ; 141.17,62.33 J11.4 ; J11.4 141.99,61.52 ; J11.4 142.8,62.33 ; J11.4 141.99,63.14 ; 142.06,30.05 J13.1 ; J13.1 142.06,31.67 ; J13.1 141.25,30.86 ; J26.5 35.17,9.82 ; J26.5 34.49,9.14 ; J26.5 35.84,9.14 ; 63.29,6.47 J19.14 ; J19.14 62.61,7.14 ; J19.14 63.29,7.82 ; J19.14 63.96,7.14 ; J27.1 43.18,7.19 ; J27.1 43.18,5.31 ; J27.1 44.12,6.25 ; J27.1 42.24,6.25 ; J26.13 27.84,9.14 ; J26.13 26.49,9.14 ; J26.13 27.17,8.47 ; J26.13 27.17,9.82 ; 79.3,5.31 J21.1 ; J21.1 78.36,6.25 ; J21.1 79.3,7.19 ; J21.1 80.24,6.25 ; 63.69,92.39 J8.S4 ; J8.S4 63.69,95.65 ; J8.S4 65.31,94.02 ; J26.14 27.17,7.82 ; J26.14 26.49,7.14 ; J26.14 27.17,6.47 ; J26.14 27.84,7.14 ; 45.21,5.31 J27.2 ; J27.2 44.27,6.25 ; J27.2 45.21,7.19 ; 142.01,14.81 J14.2 141.2,14 ; J6.4 60.43,75.92 ; J6.4 59.15,75.92 ; J6.4 59.79,75.11 ; J6.4 59.79,76.73 ; 14.49,7.14 J26.26 ; J26.26 15.84,7.14 ; J26.26 15.17,7.82 ; J26.26 15.17,6.47 ; J14.8 142.01,27 ; J14.8 141.2,26.19 ; J14.8 142.01,25.37 ; 42.45,88.83 J5.20 ; J5.20 44.03,87.25 ; J5.20 45.6,88.83 ; J5.20 44.03,90.4 ; J9.13 85.04,89.38 ; J9.13 84.37,88.7 ; J9.13 85.04,88.02 ; J9.13 85.72,88.7 ; 63.6,75.11 J6.1 ; J6.1 63.6,76.73 ; J6.1 62.96,75.92 ; J6.1 64.24,75.92 ; J8.S3 76.83,95.65 ; J8.S3 78.46,94.02 ; J8.S3 75.2,94.02 ; J8.S3 76.83,92.39 ; 63.69,86.72 J8.S2 ; J8.S2 63.69,89.97 ; J8.S2 65.31,88.34 ; 66.27,75.07 J6.8 ; J6.8 64.92,76.42 ; J6.8 67.62,76.42 ; J6.8 66.27,77.77 ; J21.2 81.33,7.19 ; J21.2 81.33,5.31 ; J21.2 80.39,6.25 ; 117.44,74.55 U36.MH1 ; U36.MH1 117.44,80.91 ; U36.MH1 120.61,77.73 ; U36.MH1 114.26,77.73 ; 34.49,7.14 J26.6 ; J26.6 35.17,6.47 ; J26.6 35.84,7.14 ; 66.08,91.34 J8.4 ; J8.4 66.76,92.02 ; J8.4 67.43,91.34 ; J8.4 66.76,90.66 ; J5.13 47.1,90.04 ; J5.13 47.83,89.31 ; J5.13 46.36,89.31 ; J5.16 50.6,88.54 ; J5.16 50.6,87.07 ; J5.16 51.33,87.81 ; J5.16 49.86,87.81 ; J8.S1 78.46,88.34 ; J8.S1 75.2,88.34 ; J8.S1 76.83,89.97 ; J8.S1 76.83,86.72 ; 127.71,78.18 H5.1 ; H5.1 131.67,78.18 ; H5.1 129.69,80.16 ; H5.1 129.69,76.2 ; J7.2 74.52,77.42 ; J7.2 73.71,76.61 ; J7.2 74.52,75.79 ; J7.2 75.34,76.61 ; J5.19 58.74,88.83 ; J5.19 55.59,88.83 ; J5.19 57.17,87.25 ; J9.4 85.04,92.02 ; J9.4 85.04,90.66 ; J9.4 84.37,91.34 ; J9.4 85.72,91.34 ; 141.25,41.02 J13.6 ; J13.6 142.06,41.83 ; J13.6 142.06,40.21 ; 46.36,92.51 J5.4 ; J5.4 47.83,92.51 ; J5.4 47.1,93.24 ; J8.13 66.76,89.38 ; J8.13 67.43,88.7 ; J8.13 66.08,88.7 ; J8.13 66.76,88.02 ; 49.86,91.01 J5.7 ; J5.7 51.33,91.01 ; J5.7 50.6,90.27 ; J5.7 50.6,91.74 ; 81.97,86.72 J9.S2 ; J9.S2 80.35,88.34 ; J9.S2 83.6,88.34 ; J9.S2 81.97,89.97 ; 53.31,75.07 J6.9 ; J6.9 54.66,76.42 ; J6.9 53.31,77.77 ; J6.9 51.96,76.42 ; 141.15,72.87 J12.4 ; J12.4 141.96,73.69 ; J12.4 142.77,72.87 ; J12.4 141.96,72.06 ; J19.4 73.29,7.82 ; J19.4 73.29,6.47 ; J19.4 73.96,7.14 ; J19.4 72.61,7.14 ; 81.97,92.39 J9.S4 ; J9.S4 80.35,94.02 ; J9.S4 81.97,95.65 ; J9.S4 83.6,94.02 ; 44.03,92.93 J5.21 ; J5.21 42.45,94.51 ; J5.21 45.6,94.51 ; 36.9,91.44 J18.20 ; J18.20 35.97,93.37 ; J18.20 37.82,93.37 ; 55.98,75.11 J6.7 ; J6.7 55.34,75.92 ; J6.7 55.98,76.73 ; J6.7 56.62,75.92 ; 140.64,100.33 SW1.3 ; SW1.3 139.81,101.16 ; SW1.3 141.47,101.16 ; 103.43,87.32 J30.10 102.49,86.38 ; 122.45,86.38 J31.10 ; J31.10 123.39,87.32 ; J31.10 121.51,87.32 ; J31.10 122.45,88.26 ; 63.29,8.47 J19.13 ; J19.13 62.61,9.14 ; J19.13 63.29,9.82 ; J19.13 63.96,9.14 ; J16.1 137.85,11.94 ; J16.1 135.97,11.94 ; J16.1 136.91,11 ; 55.59,94.51 J5.22 58.74,94.51
  VCC w1.016: J26.6 J26.5
  VCC w1.524: J5.22 J5.19
  GND w0.508: 47.37,90.3 47.1,90.02 J5.13 48.03,89.31 48.13,89.41
  GND w0.686: J26.26 15.84,7.14 ; J26.26 14.49,7.14 ; J26.26 15.17,7.82 ; J26.26 15.17,6.47 ; 59.15,75.92 J6.4 ; J6.4 59.79,76.73 ; J6.4 60.43,75.92 ; J6.4 59.79,75.11 ; J18.23 37.82,99.33 ; J18.23 36.9,97.9 ; J18.23 36.9,100.76 ; J18.23 35.97,99.33 ; J5.19 57.17,90.4 ; J5.19 55.59,88.83 ; J5.19 58.74,88.83 ; J5.19 57.17,87.25 ; J9.S4 81.97,95.65 ; J9.S4 81.97,92.39 ; J9.S4 80.35,94.02 ; J9.S4 83.6,94.02 ; 22.4,91.44 J18.21 ; J18.21 21.47,93.37 ; J18.21 22.4,95.3 ; J18.21 23.32,93.37 ; 36.9,91.44 J18.20 ; J18.20 35.97,93.37 ; J18.20 36.9,95.3 ; J18.20 37.82,93.37 ; 102.49,86.38 J30.10 ; J30.10 101.55,87.32 ; J30.10 102.49,88.26 ; J30.10 103.43,87.32 ; J5.7 51.33,91.01 ; J5.7 49.86,91.01 ; J5.7 50.6,90.27 ; J5.7 50.6,91.74 ; 14.49,9.14 J26.25 ; J26.25 15.17,8.47 ; J26.25 15.17,9.82 ; J26.25 15.84,9.14 ; 84.37,88.7 J9.13 ; J9.13 85.04,89.38 ; J9.13 85.04,88.02 ; J9.13 85.72,88.7 ; 114.26,77.73 U36.MH1 ; U36.MH1 117.44,74.55 ; U36.MH1 117.44,80.91 ; U36.MH1 120.61,77.73 ; J8.S3 78.46,94.02 ; J8.S3 75.2,94.02 ; J8.S3 76.83,92.39 ; J8.S3 76.83,95.65 ; J27.1 44.12,6.25 ; J27.1 43.18,5.31 ; J27.1 42.24,6.25 ; J27.1 43.18,7.19 ; J8.4 66.76,92.02 ; J8.4 66.76,90.66 ; J8.4 66.08,91.34 ; J8.4 67.43,91.34 ; J5.22 58.74,94.51 ; J5.22 57.17,96.08 ; J5.22 57.17,92.93 ; J5.22 55.59,94.51 ; 34.49,9.14 J26.5 ; J26.5 35.17,8.47 ; J26.5 35.84,9.14 ; J26.5 35.17,9.82 ; 55.98,75.11 J6.7 ; J6.7 56.62,75.92 ; J6.7 55.98,76.73 ; J6.7 55.34,75.92 ; J9.S2 83.6,88.34 ; J9.S2 80.35,88.34 ; J9.S2 81.97,89.97 ; J9.S2 81.97,86.72 ; J5.4 47.83,92.51 ; J5.4 47.1,93.24 ; J5.4 46.36,92.51 ; 84.37,91.34 J9.4 ; J9.4 85.04,90.66 ; J9.4 85.04,92.02 ; J9.4 85.72,91.34 ; SW1.2 139.92,99.21 ; SW1.2 138.26,99.21 ; SW1.2 139.09,98.38 ; SW1.2 139.09,100.04 ; 45.21,5.31 J27.2 ; J27.2 44.27,6.25 ; J27.2 45.21,7.19 ; J8.S1 78.46,88.34 ; J8.S1 76.83,86.72 ; J8.S1 75.2,88.34 ; J8.S1 76.83,89.97 ; J19.13 63.29,9.82 ; J19.13 63.29,8.47 ; J19.13 62.61,9.14 ; J19.13 63.96,9.14 ; J5.21 44.03,96.08 ; J5.21 42.45,94.51 ; J5.21 44.03,92.93 ; J5.21 45.6,94.51 ; 141.2,26.19 J14.8 ; J14.8 142.01,25.37 ; J14.8 142.82,26.19 ; J14.8 142.01,27 ; J26.6 35.84,7.14 ; J26.6 34.49,7.14 ; J26.6 35.17,7.82 ; J26.6 35.17,6.47 ; 127.71,78.18 H5.1 ; H5.1 129.69,80.16 ; H5.1 131.67,78.18 ; H5.1 129.69,76.2 ; J18.22 22.4,100.76 ; J18.22 23.32,99.33 ; J18.22 21.47,99.33 ; J18.22 22.4,97.9 ; J6.8 67.62,76.42 ; J6.8 64.92,76.42 ; J6.8 66.27,77.77 ; J6.8 66.27,75.07 ; J13.6 142.06,41.83 ; J13.6 142.06,40.21 ; J13.6 141.25,41.02 ; J13.6 142.88,41.02 ; J5.20 45.6,88.83 ; J5.20 44.03,90.4 ; J5.20 44.03,87.25 ; J5.20 42.45,88.83 ; J26.13 27.17,9.82 ; J26.13 27.17,8.47 ; J26.13 26.49,9.14 ; J26.13 27.84,9.14 ; J6.9 54.66,76.42 ; J6.9 53.31,75.07 ; J6.9 51.96,76.42 ; J6.9 53.31,77.77 ; 15.34,96.09 LED1.2 ; LED1.2 16.23,96.98 ; LED1.2 14.45,96.98 ; LED1.2 15.34,97.87 ; J19.14 63.96,7.14 ; J19.14 63.29,6.47 ; J19.14 62.61,7.14 ; J19.14 63.29,7.82 ; J11.4 141.99,63.14 ; J11.4 141.17,62.33 ; J11.4 142.8,62.33 ; J11.4 141.99,61.52 ; 27.17,6.47 J26.14 ; J26.14 26.49,7.14 ; J26.14 27.17,7.82 ; J26.14 27.84,7.14 ; 141.96,72.06 J12.4 ; J12.4 141.96,73.69 ; J12.4 142.77,72.87 ; J12.4 141.15,72.87 ; J16.1 137.85,11.94 ; J16.1 135.97,11.94 ; J16.1 136.91,11 ; J21.2 81.33,7.19 ; J21.2 81.33,5.31 ; J21.2 80.39,6.25 ; 141.27,51.69 J10.4 ; J10.4 142.9,51.69 ; J10.4 142.09,50.88 ; J10.4 142.09,52.5 ; 73.71,76.61 J7.2 ; J7.2 74.52,77.42 ; J7.2 74.52,75.79 ; J7.2 75.34,76.61 ; 141.2,14 J14.2 ; J14.2 142.01,13.18 ; J14.2 142.82,14 ; J14.2 142.01,14.81 ; J8.13 67.43,88.7 ; J8.13 66.76,89.38 ; J8.13 66.76,88.02 ; J8.13 66.08,88.7 ; J6.1 64.24,75.92 ; J6.1 63.6,75.11 ; J6.1 63.6,76.73 ; J6.1 62.96,75.92 ; J5.16 51.33,87.81 ; J5.16 49.86,87.81 ; J5.16 50.6,88.54 ; J5.16 50.6,87.07 ; 140.64,100.33 SW1.3 ; SW1.3 139.81,101.16 ; SW1.3 141.47,101.16 ; J19.4 73.29,7.82 ; J19.4 73.29,6.47 ; J19.4 72.61,7.14 ; J19.4 73.96,7.14 ; J13.1 142.06,31.67 ; J13.1 142.88,30.86 ; J13.1 142.06,30.05 ; J13.1 141.25,30.86 ; 121.51,87.32 J31.10 ; J31.10 123.39,87.32 ; J31.10 122.45,86.38 ; J31.10 122.45,88.26 ; 63.69,86.72 J8.S2 ; J8.S2 65.31,88.34 ; J8.S2 63.69,89.97 ; J9.S1 96.74,88.34 ; J9.S1 95.12,89.97 ; J9.S1 95.12,86.72 ; J9.S1 93.49,88.34 ; 62.06,94.02 J8.S4 ; J8.S4 65.31,94.02 ; J8.S4 63.69,95.65 ; J8.S4 63.69,92.39 ; 79.3,5.31 J21.1 ; J21.1 78.36,6.25 ; J21.1 79.3,7.19 ; J21.1 80.24,6.25 ; 95.12,92.39 J9.S3 ; J9.S3 95.12,95.65 ; J9.S3 93.49,94.02 ; J9.S3 96.74,94.02
  BOTTOM w0.127: v2(112.62,71.93) 112.62,71.83 112.55,71.75 112.55,68.96 v2(112.62,68.88) 112.62,68.86 112.47,68.71 112.47,64.97 107.95,60.45 99.06,60.45 95,56.39 95,52.83 v2(94.59,52.43) 94.67,52.35 94.67,51.77 94.46,51.56 94.03,51.56 v2(93.95,51.49) 93.9,51.49 93.6,51.18 93.6,50.55 93.73,50.42 94.53,50.42 v2(94.6,50.5) 94.95,50.5 95.5,51.05 95.5,56.13 97,57.63 v2(97.21,57.63) ; v2(94.34,53.39) 94.34,56.49 98.81,60.96 107.7,60.96 107.84,61.11 111.94,65.2 111.94,70.97 v2(111.46,71.45) ; v2(123.7,20.95) 122.43,22.23 120.02,22.23 115.44,26.8 v2(112.14,26.8) 106.72,26.8 103.67,29.84 v2(101.6,29.84) C34.1 98.6,29.87 98.12,30.35 95.54,30.35 95.39,30.2 v2(95,30.2) ; v2(124.99,70.79) 125.93,70.79 128.27,68.45 128.27,67.06 131.83,63.5 131.83,48.01 128.79,44.97 119.77,44.97 116.46,41.66 115.19,41.66 114.81,42.04 111.63,42.04 110.24,43.43 100.71,43.43 97.08,39.8 v2(95.25,39.8) ; C197.1 98.42,50.5 v2(98.42,50.93) 98.42,53.34 v2(98.68,53.59) 99.19,53.59 99.31,53.47 99.62,53.47 C494.1 ; C197.1 99.37,49.55 v2(100.18,49.55) 100.84,48.89 100.84,48.39 102.36,46.86 128.02,46.86 129.67,48.51 129.67,57.15 v2(128.78,58.04) 125.73,61.09 125.73,66.55 v2(124.97,67.31) ; C197.1 98.52,49.92 v2(98.17,49.92) ; v2(109.75,67.64) 109.75,65.89 106.85,62.99 103.51,62.99 103.13,63.37 101.1,63.37 100.72,62.99 98.17,62.99 93.47,58.29 92.53,58.29 91.89,57.66 v2(91.89,57.55) ; v2(124.71,66.29) 124.97,66.04 124.97,60.58 v2(127.13,58.42) 128.91,56.64 128.91,49.02 v2(128.52,48.64) 127.51,47.62 102.77,47.62 v2(102.13,48.26) 102.13,48.62 99.56,51.19 99.56,52.39 C494.1 ; v2(97.21,57.63) 97.21,57.84 98.81,59.44 ; v2(97.21,57.63) 97.43,57.4 97.89,57.4 98.4,57.91 100.46,57.91 100.97,57.4 108.2,57.4 110.11,59.31 110.11,61.09 111.25,62.23 112.65,62.23 112.78,62.36 112.78,62.99 112.5,63.27 v2(112.01,63.27) ; v2(91.92,58.7) 92.13,58.9 93.04,58.9 93.07,58.93 93.09,58.93 97.66,63.5 100.51,63.5 100.89,63.88 103.34,63.88 103.72,63.5 106.64,63.5 108.94,65.8 v2(108.94,67.77) ; 97.08,70.79 95.63,69.34 95.63,65.66 v2(95,65.02) v2(94.61,64.64) v2(92.96,62.99) ; C494.1 100.25,53.09 v2(100.58,53.09) 100.71,53.09 100.84,53.21 102.29,53.21 v2(102.49,53.42) 103.45,53.42 104.01,53.98 v2(122.3,53.98) 123.02,53.98 123.62,54.57 v2(123.62,57.02) ; C494.1 100.12,52.53 100.58,52.07 101.22,52.07 101.5,52.35 v2(101.5,52.4) 103.71,52.4 104.39,53.09 v2(120.65,53.09) 121.04,53.09 121.3,52.83 122.94,52.83 124.46,54.36 124.46,57.88 v2(122.17,60.17) 120.65,61.69 v2(120.65,63.75) ; 101.17,69.6 96.93,69.6 v2(96.29,68.96) 96.14,68.81 96.14,65.91 ; C163.1 104.44,57.91 101.78,57.91 C153.1 100.76,58.93 99.95,58.93 99.59,59.28 v2(99.59,59.44) 98.81,59.44 ; 96.14,65.91 96.77,66.55 ; 96.14,65.91 96.14,64.98 92.96,61.81 v2(92.77,61.81) 92.07,61.81 90.17,59.9 90.17,57.02 88.9,55.75 88.9,55.24 88.04,54.38 v2(88.04,53.34) 88.04,53.31 88.27,53.09 88.62,53.09 v2(88.87,53.34) 88.87,54.46 89.41,54.99 89.41,55.5 90.68,56.77 90.68,59.69 92.08,61.09 93.07,61.09 97.01,65.02 99.03,65.02 v2(99.17,65.16) 99.2,65.16 99.44,65.41 103.5,65.41 103.89,65.79 103.89,66.29 104.39,66.8 ; C95.1 95,22.63 92.94,22.63 91.57,24 91.57,25.04 v2(91.08,25.53) 88.42,28.19 85.09,28.19 81.79,31.5 75.06,31.5 74.04,30.48 71.63,30.48 70.61,31.5 v2(70.61,33.17) ; 98.81,59.44 99.31,59.94 108.2,59.94 111.53,63.27 v2(112.01,63.27) ; v2(124.97,71.63) 125.02,71.63 125.15,71.5 125.98,71.5 128.78,68.71 128.78,67.31 132.33,63.75 132.33,47.37 v1(131.32,46.35) 129.29,44.32 v2(127.51,44.32) v2(125.23,44.32) v2(123.75,44.32) 119.89,44.32 116.71,41.15 114.94,41.15 114.55,41.53 111.14,41.53 v2(110.59,42.08) 109.75,42.93 100.97,42.93 96.72,38.68 v2(95.25,38.68) ; v2(98.24,56.46) 98.25,56.45 98.25,56.3 98.68,55.88 100.33,55.88 100.58,55.63 102.23,55.63 ; v2(94.69,29.84) 94.69,29.64 95.25,29.08 103.72,29.08 106.76,26.04 115.44,26.04 119.76,21.72 121.79,21.72 122.05,21.46 122.05,17.53 v2(121.79,17.27) ; 102.23,55.63 v2(102.36,55.63) 103.12,55.63 103.5,55.24 v2(103.5,54.99) ; 102.23,55.63 101.47,54.86 97.16,54.86 96.52,54.23 96.52,46.74 97.28,45.97 97.79,45.97 99.06,44.7 111.63,44.7 112.66,43.67 v2(112.66,43.52) ; v2(113.89,43.54) 112.22,45.21 99.36,45.21 98.09,46.48 97.54,46.48 97.03,46.99 97.03,53.98 97.41,54.36 102.87,54.36 v2(103.5,54.99) ; 21.54,29.79 21.54,26.62 21.21,26.29 20.59,26.29 R107.2 ; v2(81.92,24.64) 81.78,24.78 81.78,25.77 v2(81.92,25.91) ; v2(103.5,54.99) 103.84,54.99 104.47,55.63 108.71,55.63 115.57,62.48 115.57,63.12 115.29,63.4 114.07,63.4 v2(113.79,63.12) ; 101.45,70.21 101.45,70.18 ; v2(112.01,63.27) 113.03,64.29 113.03,67.11 113.74,67.82 113.97,67.82 R241.2 114.35,68.2 v2(114.83,68.2) ; v2(73.03,32.51) 73.53,33.02 82.55,33.02 85.85,29.72 89.41,29.72 93.09,26.04 93.09,24.89 93.73,24.26 96.8,24.26 97.92,23.14 97.92,22.4 97.74,22.23 97.74,21.72 v2(97.71,21.69) 97.74,21.67 U13.11 ; v2(49.94,50.72) 50.6,50.72 50.77,50.9 50.77,72.01
  BOTTOM w0.203: U35.18 67.93,37.81 68.07,37.67 v2(68.07,37.08) ; v2(100.58,73.66) v2(100.58,74.68) 100.36,74.9 100.36,75.41 v2(100.08,75.69) v2(98.93,75.69) v2(97.79,75.69) ; C193.1 v2(116.43,73.3) 116.1,73.63 112.8,73.63 112.5,73.33 v2(112.5,72.95) 112.5,69.62 112.7,69.42 116.89,69.42 v2(116.92,69.44) ; 97.31,70.91 97.2,70.91 97.08,70.79 ; 97.31,70.91 C171.1 ; 97.31,70.91 96.77,71.45 96.77,74.08 97.5,74.81 XT4.4 ; C14.1 v1(49.33,30.63) ; C171.1 R194.2 100.13,70.91 v2(100.58,71.37) ; C171.1 98.81,71.41 XT4.2 99.5,71.9 v2(100.58,71.9) ; XT1.4 82.11,72.45 81.85,72.71 81.85,74.87 82.09,75.11 v2(83.64,75.11) 85.3,75.11 v2(85.37,75.18) 85.8,75.18 86.05,74.94 86.05,74.86 86.11,74.8 86.11,71.48 v2(85.93,71.3) ; 84.33,67.34 85,68.01 85.15,68.01 85.5,68.35 85.5,69.75 85.93,70.18 C65.1 ; v2(67.44,36.7) 67.31,36.58 66.88,36.58 66.61,36.84 U35.20 66.61,38.21 U35.25 v2(66.61,39.41) U35.11 ; R10.2 v1(49.38,31.7)
  BOTTOM w0.254: v2(6.35,39.37) 6.35,39.89 6.22,40.01 TP18.1 ; R29.2 63.37,81.41 v2(63.37,81.81) ; C270.1 90.5,37.49 91.03,38.02 93.63,38.02 v2(93.96,37.69) ; TP22.1 7.11,61.72 v2(7.62,62.23) ; v2(89.66,14.22) 88.9,14.99 ; 88.9,14.99 88.9,12.76 94.52,7.14 102.77,7.14 104.78,9.14 125.6,9.14 133.35,16.89 ; 88.9,14.99 88.9,19.24 88.52,19.62 v2(88.52,19.99) ; TP19.1 3.39,25.74 v2(4.32,25.74) ; U8.24 84.13,67.14 84.33,67.34 ; v2(92.99,17.78) 92.99,17.48 94.11,16.36 v2(94.11,15.24) ; v1(136.31,18.58) 126.11,8.38 105.28,8.38 103.12,6.22 94.36,6.22 87.88,12.7 v2(87.88,19.99) ; v2(5.08,53.21) 5.46,53.59 TP17.1 ; v2(93.34,12.74) 92.84,13.25 v2(92.84,13.97) 92.84,16.18 91.97,17.04 v2(91.97,17.53) ; v2(8.89,10.92) TP21.1 ; 86.97,18.61 v2(86.97,17.09) ; R296.1 13.5,47.13 13.89,46.74 v1(15.11,46.74) ; v2(7.37,17.99) 7.37,17.4 TP20.1
  BOTTOM w0.305: v2(49.91,22.61) 49.78,22.61 49.5,22.33 J23.11 ; U20.2 v1(33.63,58.42) 33.69,58.36 C147.1 ; C150.1 34.28,54.29 v1(33.91,54.66) 32.67,54.66 U21.2 v1(31.65,54.74) ; v2(54.99,22.5) 54.99,21.55 J23.22 ; v1(59.85,83.73) C9.1 v1(59.85,81.83) ; J23.28 58,22.41 v2(57.91,22.5) ; J22.34 31.29,22.51 v2(31.09,22.71) ; 32.51,20.32 32.79,20.59 J22.37 ; v2(61.21,22.5) 61,22.3 J23.34 ; J24.1 72.82,22.31 72.52,22.61 71.68,22.61 v2(71.55,22.48) ; 26.81,20.66 26.81,20.69 26.79,20.71 J22.25 ; J23.25 56.5,22.37 v2(56.64,22.5) ; Q2.2 v2(102.84,8.8) ; 28.29,20.7 J22.28 28.29,22.73 27.89,23.13 D53.8 ; v2(29.79,22.4) J22.31 v2(29.79,20.52) ; J23.16 52,22.44 v2(51.94,22.5) ; v2(59.56,22.5) 59.5,22.45 J23.31 ; C143.1 34.53,62.17 v2(34.37,62.33) v2(33.96,62.33) ; v2(53.34,22.5) 53.51,22.34 J23.19 ; J23.37 v2(62.5,22.51) ; U8.10 v2(78.36,63.62)
  BOTTOM w0.381: v2(20.24,52.66) 19.94,52.96 C229.1 ; v2(119.05,35.53) 118.53,35.53 118.26,35.26 C485.1 ; v2(18.8,46.74) 19,46.74 C231.1 19.38,47.19 C230.1 ; D15.8 D15.3 ; v2(75.82,17.27) 77.12,18.57 J24.8 75.97,19.99 v2(75.69,19.99) ; v2(28.07,61.47) 28.32,61.72 C144.1 ; v2(100.58,71.9) 100.59,71.89 100.93,71.89 100.93,71.89 101.16,71.89 C169.1 ; 71.02,18.8 71.02,17.71 v2(71.73,16.99) ; 71.02,18.8 J24.7 ; 71.02,18.8 72.26,17.55 v2(72.26,17.02) ; C92.1 v2(102.28,23.26) ; C92.1 101.6,23.36 v2(101.6,23.86) ; C92.1 100.68,23.26 100.58,23.36 Q1.2 ; C183.1 92.41,76.07 92.41,76.58 v2(92.43,76.61) ; v2(107.95,20.62) C91.2 ; D52.3 D52.8 ; v2(22.38,61.21) 22.25,61.09 C227.1 ; v2(97.79,75.69) 97.79,75.39 97.7,75.3 XT4.4 ; R365.2 v2(93.73,48.13) ; v2(121.41,35.66) 120.86,35.11 C274.1 120.18,35.11 v2(119.63,35.66) ; C269.1 v2(93.73,47.12) ; v2(103.38,11.3) C93.1 ; v2(64.52,18.54) 64.94,18.96 J23.42 ; D53.8 D53.3 ; v2(66.67,24.64) 66.55,24.51 C123.1 v2(65.85,25.4) ; R212.1 100.94,74.52 100.74,74.52 v2(100.58,74.68) ; C145.1 27.41,61.7 v2(27.41,61.49) ; XT5.4 v2(112.5,72.95) 112.17,73.28 C191.1 ; v2(29.34,25.15) 29.44,25.15 D54.1 ; C276.1 v1(105.01,37.4) ; v2(85.37,75.18) XT1.2 ; v2(82.04,53.34) C60.1 R45.2 ; v2(82.18,71.14) 82.18,70.61 82.07,70.51 82.07,69.75 81.99,69.67 C73.1 C76.1 82.98,69.67 83.06,69.75 83.06,70.05 83.24,70.23 C64.1 v2(83.24,71.31) 83.24,71.5 83.24,71.5 83.24,71.79 XT1.4 ; U13.2 v2(102.82,12.45) ; v2(123.62,57.02) 123.62,57.48 120.65,60.45 119.33,60.45 118.95,60.83 C211.1 118.75,61.42 R254.1 118.46,62.31 v2(118.11,62.65) ; D59.1 v2(59.89,25.45) ; R256.1 120.09,64.34 119.89,64.14 C497.1 ; C69.1 88.85,61.7 v2(89.28,62.13) ; C70.1 v2(78.99,53.34) ; C74.1 89.38,65.41 v2(89.38,65.46) 89.03,65.81 R54.2 ; v2(125.81,5.03) SIM1.C5 v2(124.64,3.3) ; U30.3 19.6,50.25 v2(19.3,50.55) ; C225.1 v2(12.17,62.87) ; v2(101.47,70.26) 101.47,70.23 101.17,69.93 101.17,69.6 ; v2(9.4,57.02) D81.3 ; C95.1 95.43,22.38 v2(95.76,22.05) ; C122.1 v2(47.24,37.59) ; C203.1 v2(113.79,63.12) ; C238.1 v2(21.03,35.08) ; C90.2 v2(108.58,17.27) ; 79.45,47.93 C268.1 ; 79.45,47.93 v2(78.87,47.93) ; 79.45,47.93 v2(79.45,48.51) ; v2(100.58,73.66) 100.91,73.66 101.17,73.4 C170.1 ; R15.2 v2(29.72,51.8) ; C118.1 31.94,24.71 D55.1 31.19,25.09 v2(31.06,25.22) ; v2(12.12,69.65) 12.14,69.62 12.19,69.62 12.34,69.47 C220.1 ; C152.1 27.8,54.94 C151.1 29.02,54.42 v2(29.21,54.61) ; D89.3 10.29,20.94 v2(10.15,21.08) ; U28.3 v2(20,57.34) ; R289.1 v2(12.4,52.88) ; v1(71.63,84.79) D19.2 71.04,84.79 71.02,84.77 U6.2 v1(71.02,82.45) ; v2(85.93,71.3) C65.1 ; R250.1 115.21,67.82 v2(114.83,68.2) ; C72.1 v2(89.18,67.28) ; v2(89.36,78.41) 89.05,78.72 89.05,79.4 R47.2 ; 96.77,66.55 v2(98.04,66.55) 98.04,66.55 v2(98.67,66.55) v2(101.6,66.55) 101.9,66.85 C496.1 R208.1 103.25,67.06 v2(103.63,67.44) 104.24,68.05 v2(104.44,68.05) ; U8.39 v2(83.13,56.46) ; C182.1 112.22,72.34 v2(112.62,71.93) ; v2(78.18,55.37) 77.98,55.17 C68.1 ; v2(74.19,25.4) D64.2 ; v2(51.05,25.65) 50.43,25.03 R117.2 ; v2(116.92,69.44) 116.43,69.93 C192.1 115.32,69.98 XT5.2 ; D65.2 v2(75.44,25.4) ; C124.1 76.96,24.61 v2(76.83,24.49) ; C272.1 121.92,35.53 v2(122.05,35.66) ; v2(112.62,68.88) 113.39,68.88 ; D61.1 v2(61.14,25.48) 61.25,25.59 C125.1 61.25,26.83 v2(61.72,27.3) ; U13.15 v2(102.82,21.03) ; v2(71.88,25.4) D62.2 ; C87.2 v2(107.95,16.76) ; v2(75.06,59.94) 74.68,60.33 C75.1 ; v2(31.88,62.38) 32.16,62.1 U19.2 ; v2(93.34,12.74) D40.2 ; D16.8 D16.3 52.73,84.61 v2(52.81,84.69) ; D57.8 D57.3 v2(55.02,25.91) ; v2(98.3,18.54) 97.74,19.1 U13.11 ; D63.2 v2(73.03,25.5) ; v2(57.91,25.65) D58.3 D58.8 ; C88.2 v2(107.95,12.95) ; v2(51.18,27.18) 50.79,27.18 R118.2 50.81,26.44 v2(51.21,26.44) ; v2(124.28,35.6) 124.28,34.64 C260.1 ; C48.1 60.5,84.63 v1(60.66,84.79) ; v2(10.29,14.86) D91.3 v2(10.29,13.47) ; C121.1 v2(45.97,37.59) ; v2(87.4,71.09) C63.1 ; R366.2 v2(78.89,44.83)
  BOTTOM w0.508: R256.1 v2(120.65,63.75) ; U38.12 91.69,39.63 v1(91.69,39.62) ; 47.5,90.17 47.1,89.77 J5.13 ; C163.1 C162.1 ; D74.2 v1(121.54,77.72) ; TP16.1 v1(12.29,72.26) D103.3 ; D89.3 v1(10.29,19.4) ; D73.2 v1(125.22,77.47) ; C209.1 v1(90.3,72.39) ; D72.2 v1(104.9,81.15) ; D71.2 v1(108.58,81.15)
  BOTTOM w0.635: C52.1 v1(68.68,82.4) 68.68,81.75 C53.1
  BOTTOM w0.686: 51.33,91.01 J5.7 50.6,90.27 ; 80.35,94.02 J9.S4 ; J9.S4 83.6,94.02 ; J9.S4 81.97,92.39 ; J9.S4 81.97,95.65 ; 84.37,88.7 J9.13 ; J9.13 85.72,88.7 ; J9.13 85.04,89.38 ; J9.13 85.04,88.02 ; J9.S2 81.97,89.97 ; J9.S2 80.35,88.34 ; J9.S2 81.97,86.72 ; J9.S2 83.6,88.34 ; 57.17,87.25 J5.19 ; J5.19 55.59,88.83 ; J5.19 57.17,90.4 ; J5.19 58.74,88.83 ; 73.29,6.32 J19.4 ; J19.4 72.46,7.14 ; J19.4 74.11,7.14 ; J19.4 73.29,7.97 ; J26.13 27.99,9.14 ; J26.13 27.17,9.97 ; J26.13 26.34,9.14 ; J26.13 27.17,8.32 ; J9.S1 95.12,89.97 ; J9.S1 96.74,88.34 ; J9.S1 95.12,86.72 ; J9.S1 93.49,88.34 ; J6.1 63.6,76.73 ; J6.1 62.96,75.92 ; J6.1 63.6,75.11 ; J6.1 64.24,75.92 ; 76.83,92.39 J8.S3 ; J8.S3 75.2,94.02 ; J8.S3 78.46,94.02 ; J8.S3 76.83,95.65 ; J14.8 142.82,26.19 ; J14.8 141.2,26.19 ; J14.8 142.01,25.37 ; J14.8 142.01,27 ; J8.4 66.76,92.02 ; J8.4 66.08,91.34 ; J8.4 66.76,90.66 ; J8.4 67.43,91.34 ; LED1.2 16.23,96.98 ; LED1.2 14.45,96.98 ; LED1.2 15.34,97.87 ; LED1.2 15.34,96.09 ; 44.03,87.25 J5.20 ; J5.20 42.45,88.83 ; J5.20 44.03,90.4 ; J5.20 45.6,88.83 ; J27.1 44.12,6.25 ; J27.1 43.18,5.31 ; J27.1 42.24,6.25 ; J6.4 60.43,75.92 ; J6.4 59.15,75.92 ; J6.4 59.79,75.11 ; J6.4 59.79,76.73 ; 44.03,92.93 J5.21 ; J5.21 42.45,94.51 ; J5.21 45.6,94.51 ; J5.21 44.03,96.08 ; 139.81,101.16 SW1.3 ; SW1.3 140.64,100.33 ; SW1.3 141.47,101.16 ; 138.26,99.21 SW1.2 ; SW1.2 139.09,98.38 ; SW1.2 139.09,100.04 ; SW1.2 139.92,99.21 ; J30.10 103.43,87.32 ; J30.10 101.55,87.32 ; J30.10 102.49,86.38 ; J30.10 102.49,88.26 ; 142.06,40.21 J13.6 ; J13.6 142.88,41.02 ; J13.6 141.25,41.02 ; J13.6 142.06,41.83 ; 135.97,11.94 J16.1 ; J16.1 137.85,11.94 ; J16.1 136.91,11 ; 80.24,6.25 J21.1 78.36,6.25 ; J12.4 141.96,73.69 ; J12.4 141.15,72.87 ; J12.4 141.96,72.06 ; J12.4 142.77,72.87 ; J31.10 123.39,87.32 ; J31.10 122.45,86.38 ; J31.10 122.45,88.26 ; J31.10 121.51,87.32 ; J18.21 22.4,95.3 ; J18.21 22.4,91.44 ; J18.21 21.47,93.37 ; J18.21 23.32,93.37 ; 44.27,6.25 J27.2 45.21,5.31 ; 85.04,90.66 J9.4 ; J9.4 85.04,92.02 ; J9.4 84.37,91.34 ; J9.4 85.72,91.34 ; J26.25 15.17,9.97 ; J26.25 14.34,9.14 ; J26.25 15.17,8.32 ; J26.25 15.99,9.14 ; 62.46,7.14 J19.14 ; J19.14 64.11,7.14 ; J19.14 63.29,7.97 ; J19.14 63.29,6.32 ; 63.69,92.39 J8.S4 ; J8.S4 63.69,95.65 ; J8.S4 62.06,94.02 ; J8.S4 65.31,94.02 ; J9.S3 95.12,95.65 ; J9.S3 93.49,94.02 ; J9.S3 95.12,92.39 ; J9.S3 96.74,94.02 ; 142.06,30.05 J13.1 ; J13.1 141.25,30.86 ; J13.1 142.88,30.86 ; J13.1 142.06,31.67 ; 51.96,76.42 J6.9 ; J6.9 53.31,77.77 ; J6.9 53.31,75.07 ; 141.2,14 J14.2 ; J14.2 142.01,14.81 ; J14.2 142.82,14 ; J14.2 142.01,13.18 ; J26.14 27.17,7.97 ; J26.14 27.17,6.32 ; J26.14 27.99,7.14 ; J26.14 26.34,7.14 ; 35.17,8.32 J26.5 ; J26.5 35.99,9.14 ; J26.5 34.34,9.14 ; 76.83,86.72 J8.S1 ; J8.S1 76.83,89.97 ; J8.S1 75.2,88.34 ; J8.S1 78.46,88.34 ; 63.69,86.72 J8.S2 ; J8.S2 63.69,89.97 ; J8.S2 65.31,88.34 ; 14.34,7.14 J26.26 ; J26.26 15.17,7.97 ; J26.26 15.17,6.32 ; J26.26 15.99,7.14 ; 63.29,8.32 J19.13 ; J19.13 64.11,9.14 ; J19.13 63.29,9.97 ; J19.13 62.46,9.14 ; 66.27,75.07 J6.8 ; J6.8 67.62,76.42 ; J6.8 66.27,77.77 ; J6.8 64.92,76.42 ; J26.6 35.17,7.97 ; J26.6 35.17,6.32 ; J26.6 35.99,7.14 ; J26.6 34.34,7.14 ; J10.4 142.09,52.5 ; J10.4 142.09,50.88 ; J10.4 142.9,51.69 ; J10.4 141.27,51.69 ; 115.01,77.73 U36.MH1 ; U36.MH1 117.44,75.3 ; U36.MH1 117.44,80.16 ; J18.20 36.9,95.3 ; J18.20 35.97,93.37 ; J18.20 36.9,91.44 ; 46.36,92.51 J5.4 ; J5.4 47.83,92.51 ; J5.4 47.1,93.24 ; J11.4 142.8,62.33 ; J11.4 141.99,63.14 ; J11.4 141.99,61.52 ; J11.4 141.17,62.33 ; J8.13 66.76,89.38 ; J8.13 66.08,88.7 ; J8.13 66.76,88.02 ; J8.13 67.43,88.7 ; 55.59,94.51 J5.22 ; J5.22 58.74,94.51 ; J5.22 57.17,96.08 ; 129.69,80.9 H5.1 129.69,75.46 ; 22.4,97.9 J18.22 ; J18.22 22.4,100.76 ; J18.22 21.47,99.33 ; J18.22 23.32,99.33 ; 35.97,99.33 J18.23 ; J18.23 36.9,97.9 ; J18.23 36.9,100.76 ; J18.23 37.82,99.33 ; 55.98,75.11 J6.7 ; J6.7 55.98,76.73 ; J6.7 56.62,75.92
  BOTTOM w1.524: J18.20 38.28,93.37
  vias: v1(0.89,8.53) v1(0.89,5.64) v1(0.89,2.74) v1(0.89,1.3) v1(1.02,98.55) v1(1.02,85.17) v1(1.02,82.27) v1(1.02,79.38) v1(1.02,76.48) v1(1.02,74.07) v1(1.02,72.24) v1(1.02,69.34) v1(1.02,66.45) v1(1.02,63.55) v1(1.02,33.66) v1(1.02,30.76) v1(1.02,29.31) v1(1.02,27.86) v1(1.02,22.07) v1(1.02,20.62) v1(1.02,17.73) v1(1.02,16.28) v1(1.02,14.83) v1(1.02,11.94) v1(1.12,96.37) v1(1.07,60.78) v1(1.07,57.89) v1(1.07,54.99) v1(1.07,53.54) v1(1.07,47.75) v1(1.07,46.3) v1(1.07,44.86) v1(1.07,43.41) v1(1.07,40.51) v1(1.07,37.62) v1(2.18,1.3) v1(3.63,1.3) v1(3.91,96.32) v1(5.08,1.3) v1(6.53,1.3) v1(7.44,65.61) v1(11.56,10.41) v1(12.32,5.33) v1(12.45,20.83) v1(12.57,11.3) v1(13.21,20.83) v1(13.59,10.41) v1(13.84,14.86) v1(13.97,22.48) v1(13.97,13.72) v1(14.1,5.33) v1(14.35,15.37) v1(14.35,14.48) v1(14.86,14.99) v1(15.93,101.04) v1(16,5.33) v1(16.38,10.29) v1(16.51,24.51) v1(17.02,14.1) v1(17.53,10.29) v1(18.16,27.43) v1(18.16,5.33) v1(18.8,10.29) v1(18.92,28.32) v1(19.05,101.07) v1(19.46,64.49) v1(20.07,32.13) v1(20.19,30.48) v1(20.19,5.33) v1(20.32,20.32) v1(20.45,27.81) v1(20.45,22.86) v1(20.83,10.29) v1(20.95,87.76) v1(20.95,87) v1(20.95,86.23) v1(21.08,30.48) v1(21.08,28.96) v1(21.21,31.24) v1(21.21,29.72) v1(21.21,20.32) v1(21.46,24.26) v1(21.46,22.86) v1(21.72,87.76) v1(21.72,87) v1(21.72,86.23) v1(21.97,31.75) v1(22.23,20.32) v1(22.23,5.33) v1(22.35,24.26) v1(22.35,22.86) v1(22.48,84.2) v1(22.66,32.66) v1(22.73,30.1) v1(22.86,10.29) v1(22.96,50.04) v1(22.99,49.05) v1(23.11,46.74) v1(23.11,14.86) v1(23.24,24.26) v1(23.39,101.07) v1(23.37,22.86) v1(23.62,16.26) v1(23.75,20.32) v1(24.13,5.33) v1(24.26,34.04) v1(24.26,30.35) v1(24.64,53.21) v1(24.64,14.86) v1(24.77,20.32) v1(24.89,78.87) v1(24.89,30.86) v1(24.89,29.72) v1(24.89,22.86) v1(25.02,51.69) v1(25.15,79.5) v1(25.27,17.65) v1(25.53,81.41) v1(25.48,50.27) v1(25.53,40.49) v1(25.53,39.95) v1(25.78,79.5) v1(25.78,17.14) v1(25.91,87.12) v1(25.91,35.69) v1(26.04,76.96) v1(26.04,32.51) v1(26.16,14.86) v1(26.29,5.33) v1(26.42,76.33) v1(26.42,16.51) v1(26.54,30.86) v1(26.54,30.1) v1(26.54,18.29) v1(26.76,76.96) v1(27.1,20.12) v1(27.18,15.75) v1(27.44,76.96) v1(27.46,50.16) v1(27.56,40.49) v1(27.56,39.98) v1(27.74,101.07) v1(27.69,87.12) v1(27.69,17.27) v1(27.69,14.99) v1(27.94,30.48) v1(28.19,19.3) v1(28.19,5.33) v1(28.7,32.38) v1(28.7,29.72) v1(28.7,16.13) v1(28.96,38.35) v1(29.21,14.99) v1(29.34,13.59) v1(29.46,87.12) v1(29.51,40.11) v1(29.59,14.22) v1(29.84,36.2) v1(29.97,29.97) v1(29.97,17.91) v1(30.1,15.62) v1(30.1,14.86) v1(30.1,5.33) v1(30.63,101.07) v1(30.71,49.53) v1(30.73,30.86) v1(30.73,29.97) v1(30.86,38.35) v1(30.86,32.13) v1(31.24,75.82) v1(31.24,20.32) v1(31.39,60.66) v1(31.37,30.1) v1(31.5,36.2) v1(31.5,19.68) v1(32.13,5.33) v1(32.38,74.55) v1(32.64,81.66) v1(32.77,10.41) v1(32.89,42.42) v1(33.02,44.32) v1(33.4,73.53) v1(33.53,101.07) v1(33.74,44.58) v1(33.78,80.52) v1(33.78,49.78) v1(33.78,43.81) v1(33.78,43.05) v1(33.91,33.02) v1(34.16,5.33) v1(34.42,88.52) v1(34.42,44.58) v1(34.42,43.81) v1(34.8,79.5) v1(35.56,78.74) v1(36.2,5.33) v1(36.45,23.11) v1(36.58,24.51) v1(36.84,71.13) v1(36.96,77.34) v1(36.96,34.85) v1(36.96,22.35) v1(37.08,24.89) v1(37.21,88.52) v1(37.21,87.76) v1(38.48,77.09) v1(38.86,71.37) v1(39.12,87.88) v1(39.75,87.12) v1(39.75,82.17) v1(39.88,48.77) v1(40.13,55.12) v1(40.26,65.79) v1(40.51,66.42) v1(40.77,101.07) v1(40.77,82.17) v1(40.77,72.26) v1(40.89,71.37) v1(40.89,22.48) v1(40.89,21.72) v1(41.15,66.93) v1(41.53,32.64) v1(41.66,22.48) v1(41.66,21.72) v1(41.66,20.95) v1(41.91,81.92) v1(41.91,67.44) v1(41.91,27.43) v1(41.91,25.91) v1(41.91,24.64) v1(42.16,75.18) v1(42.16,41.78) v1(42.16,26.67) v1(42.29,86.36) v1(42.29,32.64) v1(42.42,84.71) v1(42.42,83.41) v1(42.55,67.82) v1(42.55,21.72) v1(42.55,20.95) v1(42.67,26.16) v1(42.8,71.37) v1(42.93,74.42) v1(43.05,32.64) v1(43.31,43.05) v1(43.56,73.79) v1(43.81,79.25) v1(44.2,84.71) v1(44.2,73.15) v1(44.2,72.26) v1(44.32,82.04) v1(44.37,86.41) v1(45.11,101.07) v1(45.09,43.05) v1(45.59,86.87) v1(45.72,92.2) v1(45.97,83.82) v1(45.97,82.8) v1(45.97,81.92) v1(47.37,77.98) v1(47.75,85.22) v1(47.75,84.58) v1(47.75,81.92) v1(47.88,77.47) v1(48.01,101.07) v1(48.39,86.49) v1(49.4,84.58) v1(49.4,82.42) v1(49.53,78.23) v1(49.66,85.34) v1(50.29,86.23) v1(50.67,93.6) v1(50.8,74.93) v1(50.9,101.07) v1(51.94,73.66) v1(52.7,92.2) v1(53.47,73.66) v1(53.8,101.07) v1(54.48,78.99) v1(54.86,85.85) v1(54.86,73.66) v1(55.5,86.74) v1(56.01,77.34) v1(56.39,73.66) v1(56.69,101.07) v1(57.02,86.49) v1(57.91,74.55) v1(58.29,86.36) v1(59.18,86.36) v1(59.59,101.07) v1(59.82,77.34) v1(60.55,44.25) v1(61.72,75.69) v1(62.48,101.07) v1(62.66,44.25) v1(63.5,77.34) v1(63.78,43.18) v1(64.14,36.88) v1(64.34,83.06) v1(64.34,82.5) v1(64.8,85.5) v1(65.28,85.06) v1(65.38,101.07) v1(65.35,44.25) v1(65.84,85.67) v1(66.55,85.72) v1(66.95,43.15) v1(67.18,85.55) v1(68.07,44.27) v1(68.2,90.55) v1(68.28,101.07) v1(69.82,41.07) v1(70.03,44.27) v1(70.23,92.08) v1(70.36,89.79) v1(71.17,101.07) v1(71.5,36.91) v1(72.49,10.54) v1(72.75,15.95) v1(73.99,15.98) v1(74.07,101.07) v1(75.18,84.45) v1(75.18,83.57) v1(75.18,82.42) v1(75.23,15.98) v1(75.61,36.7) v1(75.56,33.48) v1(75.69,83.06) v1(76.45,82.68) v1(76.66,16) v1(76.96,101.07) v1(77.22,57.91) v1(77.34,51.44) v1(77.77,15.93) v1(78.69,42.6) v1(79.63,33.35) v1(79.71,36.73) v1(79.86,101.07) v1(80.26,85.47) v1(81.28,84.58) v1(82.55,15.88) v1(82.75,101.07) v1(83.31,38.73) v1(83.44,79.76) v1(83.69,15.88) v1(84.2,79.76) v1(84.96,79.76) v1(85.29,16.15) v1(85.65,101.07) v1(85.72,79.76) v1(86.49,90.68) v1(86.61,79.76) v1(87,84.71) v1(87.76,87.63) v1(88.54,101.07) v1(88.52,92.08) v1(88.52,89.41) v1(88.65,86.11) v1(88.9,77.72) v1(89.1,57.68) v1(89.05,57.18) v1(89.23,58.14) v1(89.53,90.3) v1(89.66,87.63) v1(90.04,78.49) v1(90.81,78.74) v1(91.08,3.05) v1(91.34,59.84) v1(91.44,101.07) v1(91.44,77.6) v1(93.98,78.11) v1(94.34,101.07) v1(97.23,101.07) v1(97.92,78.23) v1(98.3,79.38) v1(100.13,101.07) v1(101.6,78.74) v1(102.11,84.2) v1(102.11,79.88) v1(103.02,101.07) v1(105.89,101.07) v1(107.77,40.67) v1(108.79,101.07) v1(111.68,101.07) v1(112.78,58.04) v1(114.58,101.07) v1(114.83,7.87) v1(115.85,58.06) v1(115.8,50.72) v1(115.9,51.59) v1(115.87,49.78) v1(117.47,101.07) v1(118.01,85.75) v1(118.21,49.71) v1(118.62,51.59) v1(118.77,49.71) v1(119.35,51.59) v1(120.07,51.59) v1(120.07,49.71) v1(120.37,101.07) v1(120.8,51.59) v1(120.8,49.71) v1(121.51,51.59) v1(121.51,49.71) v1(122.25,51.59) v1(123.85,49.35) v1(124.1,52.12) v1(124.71,101.07) v1(127.18,38.76) v1(127.28,41.4) v1(127.51,52.4) v1(127.53,51.66) v1(127.51,49.85) v1(129.06,101.07) v1(129.49,10.97) v1(130.78,12.27) v1(131.85,29.64) v1(132.16,44.32) v1(133.22,40.89) v1(133.4,101.07) v1(133.86,68.83) v1(134.19,31.93) v1(134.49,49.4) v1(135.38,58.55) v1(135.38,57.66) v1(135.38,56.64) v1(135.38,55.75) v1(135.38,54.86) v1(135.38,48.64) v1(135.38,47.75) v1(135.38,46.86) v1(135.38,45.85) v1(135.38,44.83) v1(135.51,66.55) v1(135.51,65.66) v1(135.51,64.77) v1(135.51,41.53) v1(135.51,34.16) v1(135.59,25.86) v1(135.76,22.48) v1(136.02,43.81) v1(136.02,42.93) v1(136.14,63.5) v1(136.14,62.61) v1(136.4,71.63) v1(136.4,68.71) v1(136.53,61.59) v1(136.53,51.94) v1(136.53,17.4) v1(136.91,41.66) v1(136.91,38.61) v1(137.29,51.94) v1(137.41,61.59) v1(137.54,17.4) v1(137.74,101.07) v1(137.67,68.71) v1(137.67,67.44) v1(137.79,65.66) v1(138.3,47.75) v1(138.3,46.86) v1(138.46,0.99) v1(139.19,37.08) v1(139.19,26.04) v1(139.19,23.88) v1(139.19,19.56) v1(139.32,45.97) v1(139.32,21.72) v1(139.7,65.79) v1(141.22,1.02) v1(141.53,8.89) v1(143.54,101.07) v1(143.94,99.77) v1(143.89,5.79) v1(143.92,1.37) v1(144.15,85.39) v1(144.15,82.5) v1(144.15,79.6) v1(144.2,3.53) v2(3.81,100.33) v2(5.08,24.13) v2(5.21,48.64) v2(5.21,48.11) v2(5.84,48.64) v2(5.84,48.11) v2(7.62,100.33) v2(7.62,52.07) v2(9.02,65.15) v2(9.09,31.09) v2(9.17,69.95) v2(10.16,100.33) v2(11.51,17.22) v2(11.51,16.31) v2(11.56,25.91) v2(13.97,20.07) v2(15.11,16.51) v2(15.75,15.88) v2(16.64,16.64) v2(17.02,13.08) v2(17.02,11.68) v2(20.19,11.68) v2(20.27,72.64) v2(21.49,54.99) v2(22.94,56.97) v2(22.94,56.62) v2(23.13,72.62) v2(23.24,13.72) v2(24.87,65.13) v2(26.29,13.72) v2(27.2,65.76) v2(27.28,63.8) v2(27.56,67.94) v2(28.55,28.4) v2(29.84,68.12) v2(29.84,66.42) v2(29.95,62) v2(30.61,69.22) v2(31.04,67.21) v2(31.24,58.45) v2(31.22,56.74) v2(31.62,25.3) v2(32.41,68.71) v2(32.89,66.55) v2(33.32,53.04) v2(33.4,68.45) v2(33.53,49.15) v2(33.5,48.51) v2(33.51,47.88) v2(33.91,66.67) v2(34.04,49.15) v2(34.04,48.51) v2(34.05,47.88) v2(34.16,50.67) v2(34.16,31.11) v2(34.54,72.52) v2(34.54,66.8) v2(34.67,50.67) v2(34.85,19.68) v2(34.92,17.78) v2(35.69,71.48) v2(36.96,32.77) v2(37.08,30.73) v2(37.08,28.7) v2(37.08,26.8) v2(37.34,17.91) v2(37.47,48.01) v2(37.72,67.06) v2(38.86,14.99) v2(39.76,64.26) v2(39.75,14.99) v2(39.88,68.96) v2(39.92,34.76) v2(40.01,15.49) v2(40.21,92.25) v2(40.39,68.71) v2(40.89,68.96) v2(40.89,15.49) v2(41.15,45.72) v2(41.4,68.71) v2(41.38,38.63) v2(41.4,17.91) v2(41.53,15.49) v2(41.78,64.9) v2(41.92,68.96) v2(42.29,38.61) v2(42.42,68.71) v2(42.55,72.01) v2(42.55,45.59) v2(42.67,66.04) v2(42.93,68.96) v2(43.18,5.08) v2(43.94,17.91) v2(44.83,41.53) v2(44.96,18.8) v2(45.77,46.96) v2(45.92,45.64) v2(46.15,43.81) v2(46.23,41.53) v2(46.3,68.22) v2(46.33,67.16) v2(46.33,65.96) v2(46.3,64.9) v2(46.3,56.24) v2(46.3,55.07) v2(46.33,52.73) v2(46.3,50.01) v2(46.33,48.51) v2(46.99,5.08) v2(47.55,46.94) v2(47.5,20.07) v2(47.62,41.53) v2(47.75,14.86) v2(47.9,49.71) v2(48.21,44.96) v2(48.44,64.9) v2(48.44,55.12) v2(48.44,51.38) v2(48.39,48.72) v2(48.46,67.13) v2(48.46,65.94) v2(48.51,14.86) v2(49.02,45.03) v2(49.02,41.53) v2(49.28,37.47) v2(49.28,35.81) v2(49.61,56.24) v2(49.61,55.12) v2(49.61,52.73) v2(49.63,48.39) v2(49.68,46.15) v2(49.78,41.53) v2(49.78,38.61) v2(49.78,14.73) v2(50.19,49.73) v2(51.56,67.18) v2(51.69,66.04) v2(51.82,68.73) v2(51.96,14.69) v2(53.24,41.78) v2(53.21,39.37) v2(53.82,68.81) v2(53.94,14.73) v2(54.05,37.36) v2(55.27,38.68) v2(55.88,68.99) v2(55.88,66.67) v2(56.39,67.18) v2(56.52,27.3) v2(56.5,25.52) v2(57.28,14.49) v2(57.4,30.99) v2(57.53,68.45) v2(58.17,28.96) v2(59.56,40.89) v2(59.82,68.45) v2(60.58,14.61) v2(61.72,16.13) v2(63.63,13.84) v2(65.41,39.37) v2(65.46,38.43) v2(65.79,68.83) v2(65.79,13.84) v2(66.62,38.4) v2(67.44,78.26) v2(67.67,84.58) v2(67.94,13.84) v2(68.48,75.87) v2(68.55,78.23) v2(70.59,34.29) v2(71.12,67.56) v2(72.26,63.97) v2(72.31,35.43) v2(72.38,62.61) v2(72.64,63.37) v2(72.95,33.02) v2(73.2,63.37) v2(73.66,78.92) v2(74.93,68.96) v2(75.92,79.22) v2(76.56,75.54) v2(77.11,22.45) v2(77.47,78.21) v2(77.67,77.77) v2(77.98,31.1) v2(78.11,25.78) v2(79.62,77.22) v2(79.6,75.13) v2(79.62,71.87) v2(80.67,78.38) v2(80.66,77.22) v2(81.41,36.58) v2(81.66,59.05) v2(82.17,35.56) v2(82.5,47.83) v2(82.68,36.58) v2(83.31,77.3) v2(83.87,77.27) v2(83.95,24.51) v2(84.38,77.27) v2(84.89,77.27) v2(85.42,48.67) v2(85.42,47.68) v2(85.42,45.62) v2(87.66,78.54) v2(92.71,5.08) v2(96.52,10.16) v2(96.52,5.08) v2(99.06,5.08) v2(100.97,47.37) v2(101.22,51.94) v2(101.35,47.75) v2(103.5,16.64) v2(103.5,3.81) v2(105.41,12.7) v2(105.41,10.54) v2(105.77,71.93) v2(105.77,70.87) v2(105.77,69.95) v2(106.83,71.93) v2(106.83,70.87) v2(106.83,69.95) v2(106.81,58.29) v2(107.9,71.93) v2(107.9,70.87) v2(107.9,69.95) v2(108.36,49.5) v2(109.02,49.5) v2(108.97,21.54) v2(108.99,19.53) v2(109.23,36.2) v2(111.63,19.48) v2(112.01,21.44) v2(112.13,43.54) v2(112.17,32.28) v2(112.39,77.72) v2(114.02,18.75) v2(114.96,32.33) v2(115.57,11.43) v2(115.67,17.98) v2(116.33,36.32) v2(116.46,35.69) v2(116.84,6.35) v2(117.98,51.56) v2(118.11,84.84) v2(118.11,63.75) v2(118.11,11.43) v2(118.24,60.2) v2(119.79,70.26) v2(119.79,69.19) v2(119.79,68.28) v2(120.14,63.88) v2(120.52,62.87) v2(120.65,11.43) v2(120.93,72.72) v2(120.85,70.26) v2(120.85,69.19) v2(120.85,68.28) v2(121.92,70.26) v2(121.92,69.19) v2(121.92,68.28) v2(122.05,31.67) v2(124.46,11.43) v2(128.27,8.89) v2(128.27,5.08) v2(129.34,35.99) v2(130.81,5.08) v2(131.55,23.7) v2(131.55,23.06) v2(131.55,22.43) v2(132.08,12.7) v2(132.08,10.16) v2(132.08,7.62) v2(134.62,7.62) v2(137.67,71.63) v2(137.95,29.29) v2(138.05,74.7) v2(138.3,33.96) v2(139.5,33.93) v2(140,31.01) v2(140.08,28.93) v2(140.13,27.15) v2(140.16,25.35) v2(140.39,75.54) v2(140.97,57.15) v2(141.73,82.73) v2(143.2,93.09) v2(143.2,92.53) v2(143.2,91.97) v2(143.18,91.42) v2(143.18,90.86) v2(143.18,90.3) v2(143.15,89.74)
